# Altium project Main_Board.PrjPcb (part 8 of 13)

## Sheet Power_48_20V@3A.SchDoc
size A3
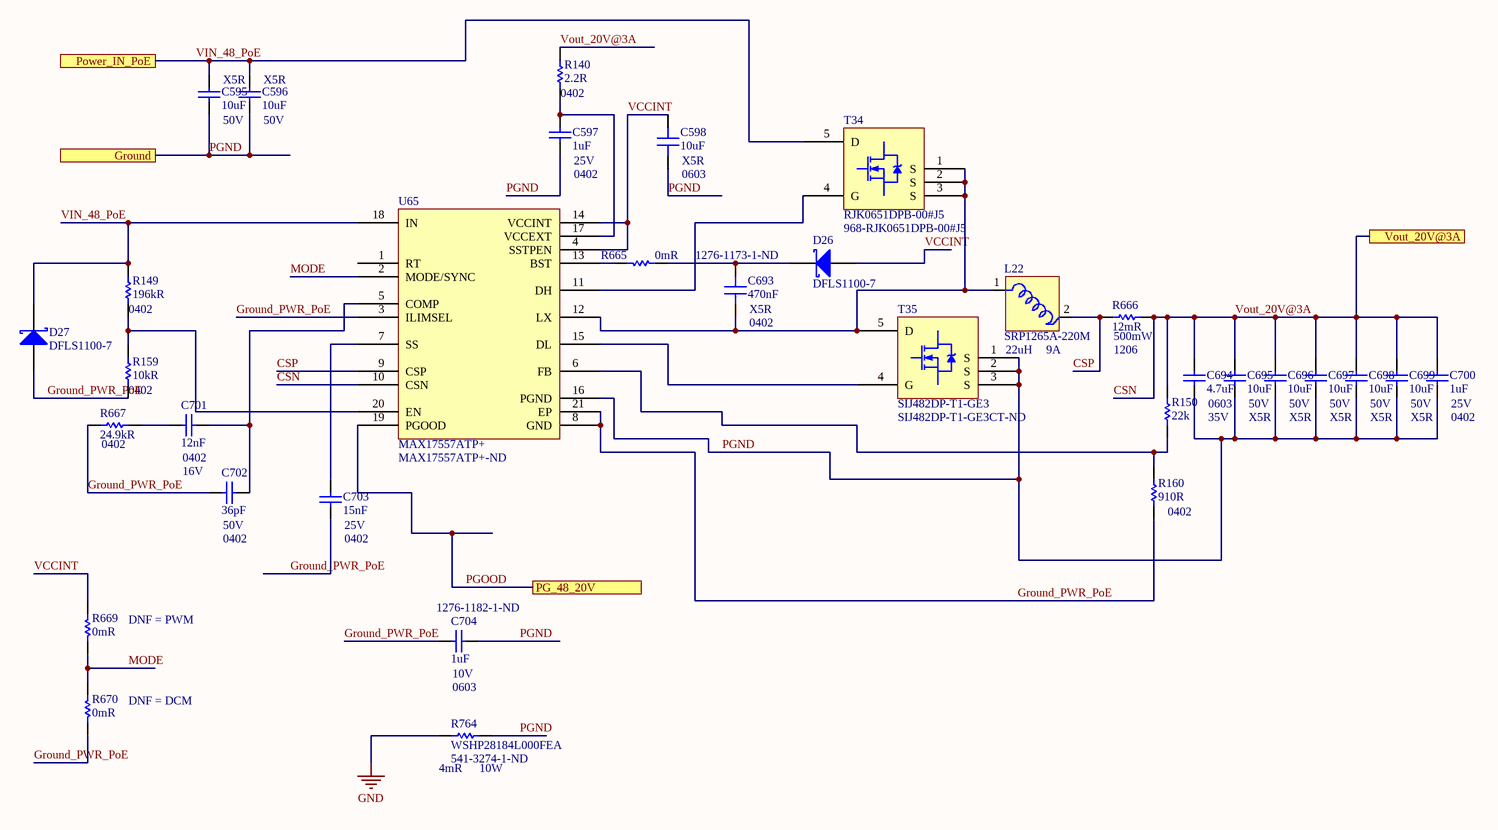
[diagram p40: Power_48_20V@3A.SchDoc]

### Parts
C595  10uF  Voltage Rating (DC): 50V  Dielectric: X5R  [CAP 0805/2012 RF]
C596  10uF  Voltage Rating (DC): 50V  Dielectric: X5R  [CAP 0805/2012 RF]
C597  1uF  Case/Package: 0402  Voltage Rating: 25V  [CAP 0402/1005 KK]
C598  10uF  Case/Package: 0603  Dielectric: X5R  [CAP 0603/1608 RF]
C693  470nF  Supplier Part Number 1: 1276-1173-1-ND  Case/Package: 0402  Dielectric: X5R  [CAP 0402/1005 KK]
C694  4.7uF  Case/Package: 0603  Voltage Rating: 35V  [CAP 0603/1608 RF]
C695  10uF  Voltage Rating (DC): 50V  Dielectric: X5R  [CAP 0805/2012 RF]
C696  10uF  Voltage Rating (DC): 50V  Dielectric: X5R  [CAP 0805/2012 RF]
C697  10uF  Voltage Rating (DC): 50V  Dielectric: X5R  [CAP 0805/2012 RF]
C698  10uF  Voltage Rating (DC): 50V  Dielectric: X5R  [CAP 0805/2012 RF]
C699  10uF  Voltage Rating (DC): 50V  Dielectric: X5R  [CAP 0805/2012 RF]
C700  1uF  Case/Package: 0402  Voltage Rating: 25V  [CAP 0402/1005 KK]
C701  12nF  Case/Package: 0402  Voltage Rating: 16V  [CAP 0402/1005 KK]
C702  36pF  Case Code (Imperial): 0402  Voltage Rating (DC): 50V  [CAP 0402/1005 KK]
C703  15nF  Case/Package: 0402  Voltage Rating: 25V  [CAP 0402/1005 KK]
C704  1uF  Supplier Part Number 1: 1276-1182-1-ND  Case/Package: 0603  Voltage Rating: 10V  [CAP 0603/1608 RF]
D26  DFLS1100-7  [DFLS1100]
D27  DFLS1100-7  [DFLS1100]
L22  SRP1265A-220M  Max DC Current: 9A  Inductance: 22uH  [SRP1265A-220M]
R140  2.2R  Case Code (Imperial): 0402  [RES 0402/1005 RF KK]
R149  196kR  Case/Package: 0402  [RES 0402/1005 RF KK]
R150  22k  [RES 0402/1005 RF KK]
R159  10kR  Case Code (Imperial): 0402  [RES 0402/1005 RF KK]
R160  910R  Case/Package: 0402  [RES 0402/1005 RF KK]
R665  0mR  [RES 0402/1005 RF KK]
R666  12mR  Case/Package: 1206  Max Power Dissipation: 500mW  [RES 1206/3216]
R667  24.9kR  Case/Package: 0402  [RES 0402/1005 RF KK]
R669  0mR  [RES 0402/1005 RF KK]
R670  0mR  [RES 0402/1005 RF KK]
R764  WSHP28184L000FEA  Resistance: 4mR  Max Power Dissipation: 10W  Supplier Part Number 1: 541-3274-1-ND  [WSHP2818]
T34  RJK0651DPB-00#J5  Supplier Part Number 1: 968-RJK0651DPB-00#J5  [RJK0651DPB]
T35  SIJ482DP-T1-GE3  Supplier Part Number 1: SIJ482DP-T1-GE3CT-ND  [SiJ482DP]
U65  MAX17557ATP+  Supplier Part Number 1: MAX17557ATP+-ND  [MAX17557]

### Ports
Ground, PG_48_20V, Power_IN_PoE, Vout_20V@3A

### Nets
GND: R764.1  [project net B503_Ground]
CSN: C694.2 C695.2 C696.2 C697.2 C698.2 C699.2 C700.2 R140.2 R150.2 R666.2 U65.10(CSN) ; port Vout_20V@3A  [also labelled Vout_20V@3A]
CSP: L22.2 R666.1 U65.9(CSP)
Ground_PWR_PoE: C702.1 C703.1 C704.1 D27.2(A) R159.1 R160.1 R667.1 R670.2 U65.3(ILIMSEL) U65.8(GND) U65.21(EP)
MODE: R669.2 R670.1 U65.2(MODE/SYNC)
PGND: C595.1 C596.1 C597.1 C598.1 C694.1 C695.1 C696.1 C697.1 C698.1 C699.1 C700.1 C704.2 R764.2 T35.1(S) T35.2(S) T35.3(S) U65.16(PGND) ; port Ground
PGOOD: U65.19(PGOOD) ; port PG_48_20V  [project net PG_48_20V]
VCCINT: C598.2 D26.2(A) R669.1 U65.4(SSTPEN) U65.14(VCCINT)
VIN_48_PoE: C595.2 C596.2 D27.1(K) R149.2 T34.5(D) U65.18(IN) ; port Power_IN_PoE  [project net V_PoE+]
NetC597_2: C597.2 R140.1 U65.17(VCCEXT)
NetC693_1: C693.1 L22.1 T34.1(S) T34.2(S) T34.3(S) T35.5(D) U65.12(LX)
NetC693_2: C693.2 D26.1(K) R665.1
NetC701_1: C701.1 R667.2
NetC701_2: C701.2 C702.2 U65.5(COMP)
NetC703_2: C703.2 U65.7(SS)
NetR149_1: R149.1 R159.2 U65.20(EN)
NetR150_1: R150.1 R160.2 U65.6(FB)
NetR665_2: R665.2 U65.13(BST)
NetT34_4: T34.4(G) U65.11(DH)
NetT35_4: T35.4(G) U65.15(DL)

Not connected (* = marked no-connect by the designer): U65 1(RT)

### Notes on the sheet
- (near R669) DNF = PWM
- (near R670) DNF = DCM

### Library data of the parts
C595 C596 C695-C699 = Capacitor: Manufacturer: Murata; Manufacturer Part Number: GRM21BR61H106KE43L; Tolerance: 10%
C597 C700 = Capacitor: MURATA - GRT155R61E105KE01D - SMD Multilayer Ceramic Capacitor, 1 µF, 25 V, 0402 [1005 Metric], ± 10%, X5R, GRT Series - SMD Multilayer Ceramic Capacitor, 1 µF, 25 V, 0402 [1005 Metric], ± 10%, X5R, GRT Series
C598 = Capacitor: Manufacturer: Murata; Manufacturer Part Number: GRM188R61A106KE69D; Tolerance: 10%; Voltage Rating: 10V
C693 = Capacitor: Manufacturer: Samsung; Manufacturer Part Number: CL05A474KP5NNNC; Tolerance: 10%; Voltage Rating: 10V
C694 = Capacitor: 0603 4.7 uF 35 V ±10% Tolerance X5R Multilayer Ceramic Chip Capacitor; Manufacturer: Murata; Manufacturer Part Number: GRM188R6YA475KE15D
C701 = Capacitor: CAP, MLCC, X7R, 0.012UF, 16V, 0402; Product Range:C Series; Capacitance:0.012 F; Capacitance Tolerance: 10%; Dielectric Characteristic:X7R; Voltage Rating:16V; Ceramic Capacitor Case:0402 [1005 Metric]; Operating Temperature ;RoHS Compliant: Yes; Manufacturer: KEMET; Manufacturer Part Number: C0402C123K4RACTU; Dissipation Factor: 3.5%
C702 = Capacitor: Ceramic Capacitor 36PF 50V, C0G, 5%, 0402, Full Reel; Manufacturer: Kyocera AVX; Manufacturer Part Number: 04025A360JAT2A
C703 = Capacitor: Cap Ceramic 0.015uF 25V X7R 10% SMD 0402 125C Paper T/R; Manufacturer: Yageo; Manufacturer Part Number: CC0402KRX7R8BB153
C704 = Capacitor: Cap Ceramic 1uF 10V X5R 10% SMD 0603 85C Paper T/R; Manufacturer: Samsung; Manufacturer Part Number: CL10A105KP8NNNC
D26 D27 = DFLS1100-7: DIODE SCHOTTKY 100V POWERDI123; Manufacturer: Diodes; Forward Voltage: 770mV; Forward Current: 1A; Peak Reverse Current: 1uA; Peak Non-Repetitive Surge Current: 50A; Max Forward Surge Current (Ifsm): 40A; Element Configuration: Single; Polarity: Standard; Capacitance: 36pF
L22 = SRP1265A-220M: Inductor Power Shielded Wirewound 22uH 20% 100KHz 20Q-Factor Carbonyl Powder 9A 37mOhm DCR Automotive T/R; Manufacturer: Bourns; Saturation Current: 12A; DC Resistance (DCR): 37mR; Self Resonant Frequency: 6MHz
R140 = Resistor: RES SMD 2.2 OHM 5% 1/16W 0402; Manufacturer: Yageo; Manufacturer Part Number: RC0402JR-072R2L; Power Rating: 62.5mW; Voltage Rating: 50V; Temperature Coefficient: 200ppm/°C; Max Power Dissipation: 63mW
R149 = Resistor: Thick Film Resistors - SMD 196K OHM 1%; Manufacturer: Yageo; Manufacturer Part Number: RC0402FR-07196KL; Power Rating: 62.5mW; Voltage Rating: 50V; Temperature Coefficient: 100ppm/°C; Max Power Dissipation: 63mW
R150 = Resistor: TE CONNECTIVITY - CRGCQ0402F22K - RES, 22K, 1%, 0402, THICK FILM
R159 = Resistor: Surface Mount Thick Film Resistor, Rc Series, 10 Kohm, 62.5 Mw, - 1%, 50 V, 0402 [1005 Metric]; Manufacturer: Yageo; Manufacturer Part Number: RC0402FR-0710KL; Voltage Rating: 50V; Power Rating: 62.5mW; Temperature Coefficient: 100ppm/°C
R160 = Resistor: RES SMD 910 OHM 5% 1/10W 0402; Manufacturer: Panasonic; Manufacturer Part Number: ERJ2GEJ911X; Power Rating: 100mW; Voltage Rating: 50V; Temperature Coefficient: 200ppm/°C
R665 R669 R670 = Resistor: Manufacturer 1: Yageo; Manufacturer Part Number 1: RC0402JR-070RL; Power Rating: 62.5mW; Tolerance: 5%; Voltage Rating: 50V; Max Power Dissipation: 63mW; Temperature Coefficient: 200ppm/°C
R666 = Resistor: RES 0.012 OHM 1% 1/2W 1206; Manufacturer: Stackpole Electronics; Manufacturer Part Number: CSR1206FK12L0; Temperature Coefficient: 100ppm/°C
R667 = Resistor: RES SMD 24.9KOHM 0.1% 1/16W 0402; Manufacturer: Panasonic; Manufacturer Part Number: ERA-2AEB2492X; Power Rating: 63mW; Voltage Rating: 25V; Temperature Coefficient: 25ppm/°C; Voltage Rating (DC): 50V
R764 = WSHP28184L000FEA: RES 0.004 OHM 1% 10W 2818; Manufacturer: Vishay; Temperature Coefficient: 200ppm/°C
T34 = RJK0651DPB-00#J5: MOSFET N-CH 60V 25A LFPAK; Manufacturer: Renesas; Rise Time: 4.4ns; Turn-On Delay Time: 8.4ns; Turn-Off Delay Time: 42ns; Fall Time: 6.8ns; Gate to Source Voltage (Vgs): 20V; Rds On Max: 14mR; Input Capacitance: 2.03nF; Max Power Dissipation: 45W; Number of Elements: 1
T35 = SIJ482DP-T1-GE3: MOSFET 80V 6.2mOhm@10V 60A N-Ch MV T-FET; Manufacturer: Vishay; Rds On Max: 6.2mR; Input Capacitance: 2.425nF; Gate to Source Voltage (Vgs): 20V; Power Dissipation: 69.4W; Turn-Off Delay Time: 72ns; Number of Elements: 1; Element Configuration: Single; On-State Resistance: 9.5MR; Turn-On Delay Time: 28ns; Threshold Voltage: 1.5V
U65 = MAX17557ATP+: IC REG CTRLR BUCK 20-TQFN; Manufacturer: Maxim

## Sheet UM78M_12_8V.SchDoc
size A4
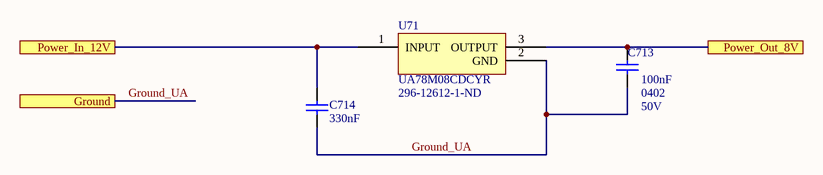
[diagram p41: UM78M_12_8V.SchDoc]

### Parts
C713  100nF  Case Code (Imperial): 0402  Voltage: 50V  [CAP 0402/1005 KK]
C714  330nF  [CAP 0603/1608 RF]
U71  UA78M08CDCYR  Supplier Part Number 1: 296-12612-1-ND  [UA78M]

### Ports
Ground, Power_In_12V, Power_Out_8V

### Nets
12V_LT3042: C714.2 U71.1(INPUT) ; port Power_In_12V
Ground_UA: C713.1 C714.1 U71.2(GND) ; port Ground  [project net AGND]
NetC713_2: C713.2 U71.3(OUTPUT) ; port Power_Out_8V

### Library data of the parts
C713 = Capacitor: CAP CER 0.1UF 50V X5R 0402; Manufacturer: Murata; Manufacturer Part Number: GRM155R61H104KE14D; Dielectric Material: Ceramic; Dissipation Factor: 0.025%; Tolerance: 10%
C714 = Capacitor: CAP CER 0.33UF 25V Y5V 0603; Manufacturer: KEMET; Manufacturer Part Number: C0603C334Z3VACTU; Dielectric Material: Ceramic; Tolerance: 80%; Dissipation Factor: 7%
U71 = UA78M08CDCYR: IC REG LINEAR 8V 500MA SOT223-4; Manufacturer: Texas Instruments; Dropout Voltage: 2V; Number of Outputs: 1; Max Input Voltage: 25V; Min Input Voltage: 10.5V; Polarity: Positive; Power Supply Rejection Ratio (PSRR): 80dB; Quiescent Current: 4.6mA; Output Type: Fixed

## Sheet TPS7A88_3V3_1V8_0V9V@2x1A.SchDoc
size A4
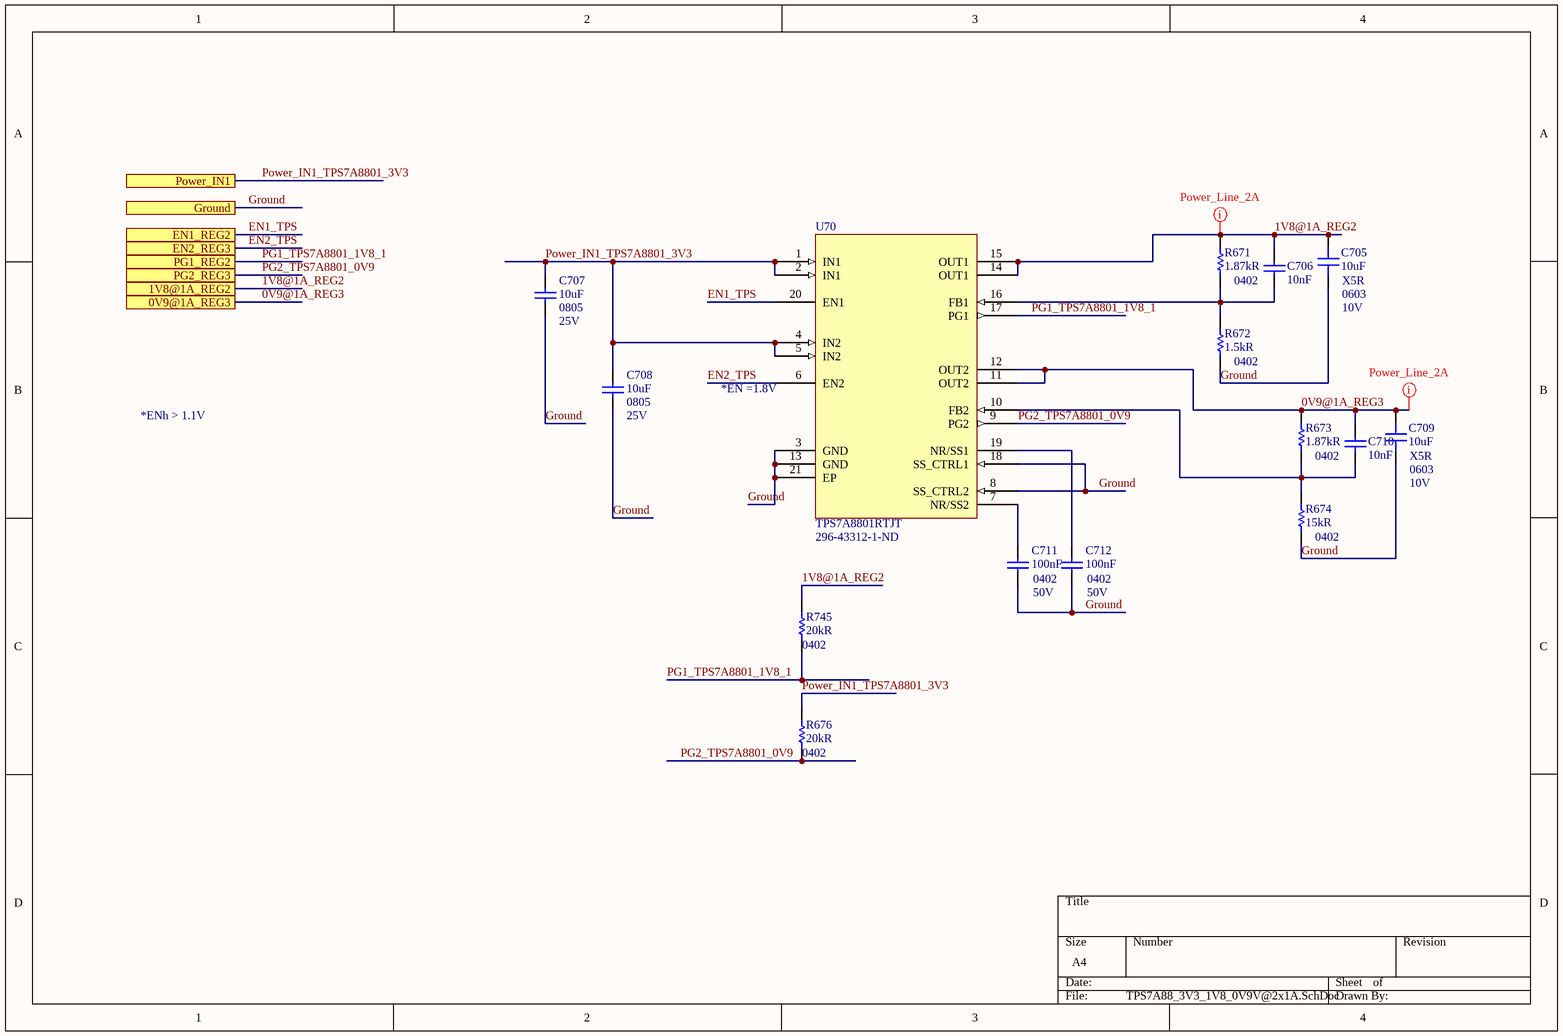
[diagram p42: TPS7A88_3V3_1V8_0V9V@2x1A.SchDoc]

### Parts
C705  10uF  Case/Package: 0603  Dielectric: X5R  Voltage Rating: 10V  [CAP 0603/1608 RF]
C706  10nF  [CAP 0201/0603 KK]
C707  10uF  Case/Package: 0805  Voltage Rating: 25V  [CAP 0805/2012 RF]
C708  10uF  Case/Package: 0805  Voltage Rating: 25V  [CAP 0805/2012 RF]
C709  10uF  Case/Package: 0603  Dielectric: X5R  Voltage: 10V  [CAP 0603/1608 RF]
C710  10nF  [CAP 0201/0603 KK]
C711  100nF  Case Code (Imperial): 0402  Voltage: 50V  [CAP 0402/1005 KK]
C712  100nF  Case Code (Imperial): 0402  Voltage: 50V  [CAP 0402/1005 KK]
R671  1.87kR  Case/Package: 0402  [RES 0402/1005 RF KK]
R672  1.5kR  Case/Package: 0402  [RES 0402/1005 RF KK]
R673  1.87kR  Case/Package: 0402  [RES 0402/1005 RF KK]
R674  15kR  Case Code (Imperial): 0402  [RES 0402/1005 RF KK]
R676  20kR  Case/Package: 0402  [RES 0402/1005 RF KK]
R745  20kR  Case/Package: 0402  [RES 0402/1005 RF KK]
U70  TPS7A8801RTJT  Supplier Part Number 1: 296-43312-1-ND  [TPS7A88]

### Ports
0V9@1A_REG3, 1V8@1A_REG2, EN1_REG2, EN2_REG3, Ground, PG1_REG2, PG2_REG3, Power_IN1

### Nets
Ground: C705.1 C707.1 C708.1 C709.1 C711.1 C712.1 R672.1 R674.1 U70.3(GND) U70.8(SS_CTRL2) U70.13(GND) U70.18(SS_CTRL1) U70.21(EP) ; port Ground  [project net B503_Ground]
0V9@1A_REG3: C709.2 C710.2 R673.2 U70.11(OUT2) U70.12(OUT2) ; port 0V9@1A_REG3
1V8@1A_REG2: C705.2 C706.2 R671.2 R745.1 U70.14(OUT1) U70.15(OUT1) ; port 1V8@1A_REG2  [project net 1V8@0.5A_ADC_filtered]
EN1_TPS: U70.20(EN1) ; port EN1_REG2
EN2_TPS: R745.2 U70.6(EN2) U70.17(PG1) ; port EN2_REG3, port PG1_REG2  [also labelled PG1_TPS7A8801_1V8_1]
PG2_TPS7A8801_0V9: R676.2 U70.9(PG2) ; port PG2_REG3
Power_IN1_TPS7A8801_3V3: C707.2 C708.2 R676.1 U70.1(IN1) U70.2(IN1) U70.4(IN2) U70.5(IN2) ; port Power_IN1  [project net 3V3_RAIL]
NetC706_1: C706.1 R671.1 R672.2 U70.16(FB1)
NetC710_1: C710.1 R673.1 R674.2 U70.10(FB2)
NetC711_2: C711.2 U70.7(NR/SS2)
NetC712_2: C712.2 U70.19(NR/SS1)

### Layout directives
net class Power_Line_2A: 0V9@1A_REG3, 1V8@0.5A_ADC_filtered

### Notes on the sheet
- *ENh > 1.1V
- (near U70) *EN =1.8V

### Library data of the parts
C705 C709 = Capacitor: Manufacturer: Murata; Manufacturer Part Number: GRM188R61A106KE69D; Tolerance: 10%
C706 C710 = Capacitor: CAP CER 10000PF 16V X7R 0201; Manufacturer: Murata; Manufacturer Part Number: GRM033R71C103KE14D; Tolerance: 10%
C707 C708 = Capacitor: CAP CER 10UF 25V X5R 0805; Manufacturer: KEMET; Manufacturer Part Number: C0805C106K3PACTU; Dielectric Material: Ceramic; Dissipation Factor: 10%
C711 C712 = Capacitor: as C713 on sheet UM78M_12_8V
R671 R673 = Resistor: Manufacturer: Panasonic; Manufacturer Part Number: ERA-2AEB1871X; Power Rating: 62.5mW; Tolerance: 0.1%; Temperature Coefficient: 25ppm/°C; Max Power Dissipation: 63mW
R672 = Resistor: Manufacturer: Panasonic; Manufacturer Part Number: ERA-2AEB152X; Power Rating: 63mW; Tolerance: 0.1%; Voltage Rating: 25V; Temperature Coefficient: 25ppm/°C
R674 = Resistor: Manufacturer: Panasonic; Manufacturer Part Number: ERJ-2RKF1502X; Tolerance: 1%; Voltage Rating: 50V; Power Rating: 100mW; Temperature Coefficient: 100ppm/°C
R676 R745 = Resistor: Manufacturer: Panasonic; Manufacturer Part Number: ERJ-2RKF2002X; Power Rating: 100mW; Tolerance: 1%; Voltage Rating: 50V; Temperature Coefficient: 100ppm/°C
U70 = TPS7A8801RTJT: IC REG LINEAR POS ADJ 1A 20QFN; Manufacturer: Texas Instruments; Output Voltage: 5V; Number of Regulators: 2; Min Current Limit: 1.5A; Quiescent Current: 2mA; Dropout Voltage: 130mV

## Sheet ADP1741_3V3_0V85.SchDoc
size A4
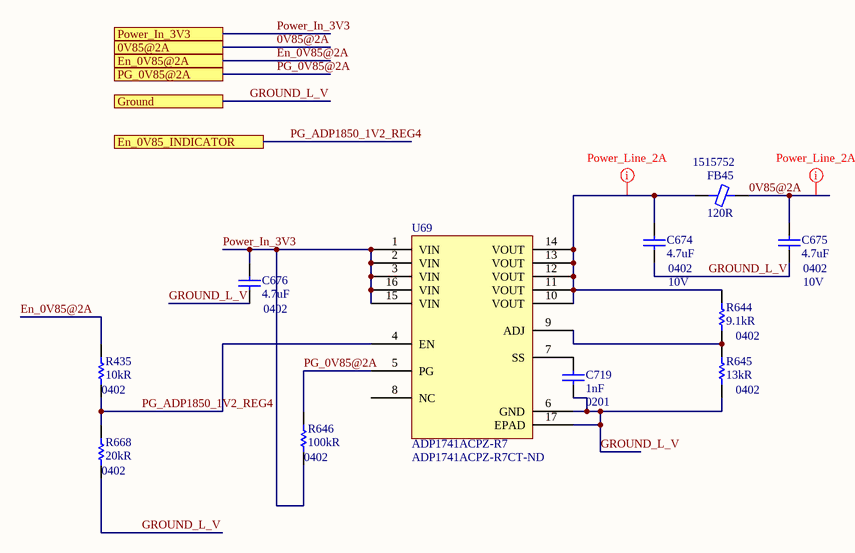
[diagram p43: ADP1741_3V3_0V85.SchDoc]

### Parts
C674  4.7uF  Case/Package: 0402  Voltage Rating: 10V  [CAP 0402/1005 KK]
C675  4.7uF  Case/Package: 0402  Voltage Rating: 10V  [CAP 0402/1005 KK]
C676  4.7uF  Case/Package: 0402  [CAP 0402/1005 KK]
C719  1nF  Case/Package: 0201  [CAP 0201/0603 KK]
FB45  120R  Supplier Part Number 1: 1515752  [FER 0603/1608]
R435  10kR  Case Code (Imperial): 0402  [RES 0402/1005 RF KK]
R644  9.1kR  Case/Package: 0402  [RES 0402/1005 RF KK]
R645  13kR  Case Code (Imperial): 0402  [RES 0402/1005 RF KK]
R646  100kR  Case/Package: 0402  [RES 0402/1005 RF KK]
R668  20kR  Case/Package: 0402  [RES 0402/1005 RF KK]
U69  ADP1741ACPZ-R7  Supplier Part Number 1: ADP1741ACPZ-R7CT-ND  [ADP1752_1753/ADP1740_1741]

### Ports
0V85@2A, En_0V85@2A, En_0V85_INDICATOR, Ground, PG_0V85@2A, Power_In_3V3

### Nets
GROUND_L_V: C674.1 C675.1 C676.1 C719.1 R645.1 R668.2 U69.6(GND) U69.17(EPAD) ; port Ground  [project net B503_Ground]
0V85@2A: C675.2 FB45.2 ; port 0V85@2A
En_0V85@2A: R435.2 ; port En_0V85@2A
PG_0V85@2A: R646.2 U69.5(PG) ; port PG_0V85@2A  [project net EN_SEQ_LT3504]
PG_ADP1850_1V2_REG4: R435.1 R668.1 U69.4(EN) ; port En_0V85_INDICATOR
Power_In_3V3: C676.2 R646.1 U69.1(VIN) U69.2(VIN) U69.3(VIN) U69.15(VIN) U69.16(VIN) ; port Power_In_3V3  [project net 3V3_RAIL]
NetC674_2: C674.2 FB45.1 R644.2 U69.10(VOUT) U69.11(VOUT) U69.12(VOUT) U69.13(VOUT) U69.14(VOUT)
NetC719_2: C719.2 U69.7(SS)
NetR644_1: R644.1 R645.2 U69.9(ADJ)

Not connected (* = marked no-connect by the designer): U69 8(NC)

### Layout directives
net class Power_Line_2A: 0V85@2A, NetC674_2

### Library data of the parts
C674 C675 = Capacitor: 0402 10 V 4.7 uF ±20% Tolerance X5R Multilayer Ceramic Chip Capacitor; Manufacturer: Murata; Manufacturer Part Number: GRM155R61A475MEAAD
C676 = Capacitor: 0402 10 V 4.7 uF ±20% Tolerance X5R Multilayer Ceramic Chip Capacitor; Manufacturer: Murata; Manufacturer Part Number: GRM155R61A475MEAAD; Voltage Rating: 10V
C719 = Capacitor: CAP CER 1000PF 25V X5R 0201; Manufacturer: Murata; Manufacturer Part Number: GRM033R61E102KA01D; Tolerance: 10%
FB45 = Ferrite: Ind Chip Bead 120Ohm 25% 100MHz Ferrite 3A 0603 Paper T/R; Manufacturer: Murata; Manufacturer Part Number: BLM18SG121TN1D; Material: Steel,Ferrite; DC Resistance (DCR): 25mR; Number of Circuits: 1; Shielding: Unshielded
R435 = Resistor: Manufacturer: Yageo; Manufacturer Part Number: RC0402FR-0710KL; Voltage Rating: 50V; Power Rating: 62.5mW; Tolerance: 1%; Temperature Coefficient: 100ppm/°C
R644 = Resistor: Manufacturer: Vishay; Manufacturer Part Number: CRCW04029K10FKED; Power Rating: 63mW; Tolerance: 1%; Voltage Rating: 50V; Temperature Coefficient: 100ppm/°C
R645 = Resistor: Manufacturer: Panasonic; Manufacturer Part Number: ERA-2AED133X; Power Rating: 62.5mW; Tolerance: 0.5%; Temperature Coefficient: 25ppm/°C; Max Power Dissipation: 63mW
R646 = Resistor: Manufacturer 1: Panasonic; Manufacturer Part Number 1: ERA-2AED104X; Tolerance: 0.5%; Power Rating: 63mW; Voltage Rating: 25V; Temperature Coefficient: 25ppm/°C
R668 = Resistor: as R676 on sheet TPS7A88_3V3_1V8_0V9V@2x1A
U69 = ADP1741ACPZ-R7: IC REG LIN POS ADJ 2A 16LFCSP; Manufacturer: Analog Devices; Output Voltage: 3V; Max Input Voltage: 3.6V; Min Input Voltage: 1.6V; Min Output Voltage: 750mV; Operating Supply Current: 1.8mA; Power Supply Rejection Ratio (PSRR): 70dB; Dropout Voltage: 160mV; Number of Outputs: 1; Min Current Limit: 2.4A; Polarity: Positive; Accuracy: 1%; Output Type: Adjustable

## Sheet ST1L08_5V_0V6.SchDoc
size A3
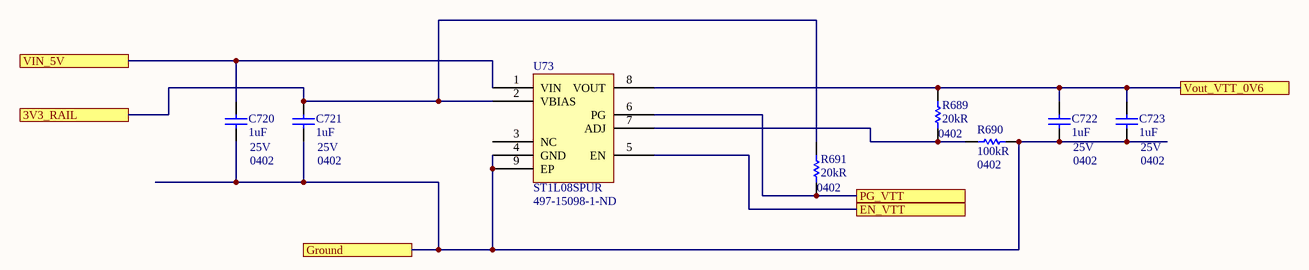
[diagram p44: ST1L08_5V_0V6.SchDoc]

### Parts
C720  1uF  Case/Package: 0402  Voltage Rating: 25V  [CAP 0402/1005 KK]
C721  1uF  Case/Package: 0402  Voltage Rating: 25V  [CAP 0402/1005 KK]
C722  1uF  Case/Package: 0402  Voltage Rating: 25V  [CAP 0402/1005 KK]
C723  1uF  Case/Package: 0402  Voltage Rating: 25V  [CAP 0402/1005 KK]
R689  20kR  Case/Package: 0402  [RES 0402/1005 RF KK]
R690  100kR  Case/Package: 0402  [RES 0402/1005 RF KK]
R691  20kR  Case/Package: 0402  [RES 0402/1005 RF KK]
U73  ST1L08SPUR  Supplier Part Number 1: 497-15098-1-ND  [ST1L08]

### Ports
3V3_RAIL, EN_VTT, Ground, PG_VTT, VIN_5V, Vout_VTT_0V6

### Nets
B503_Ground: C720.1 C721.1 C722.1 C723.1 R690.1 U73.4(GND) U73.9(EP) ; port Ground
3V3_RAIL: C721.2 R691.1 U73.2(VBIAS) ; port 3V3_RAIL
5V_RAIL: C720.2 U73.1(VIN) ; port VIN_5V
GPIOb_02.GPIO4: R691.2 U73.6(PG) ; port PG_VTT
PG2_TPS7A8801_0V9: U73.5(EN) ; port EN_VTT
RAM_DDR4_VTT: C722.2 C723.2 R689.1 U73.8(VOUT) ; port Vout_VTT_0V6
NetR689_2: R689.2 R690.2 U73.7(ADJ)

Not connected (* = marked no-connect by the designer): U73 3(NC)

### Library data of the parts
C720-C723 = Capacitor: as C597 on sheet Power_48_20V@3A
R689 R691 = Resistor: as R676 on sheet TPS7A88_3V3_1V8_0V9V@2x1A
R690 = Resistor: as R646 on sheet ADP1741_3V3_0V85
U73 = ST1L08SPUR: IC REG LINEAR POS ADJ 800MA 8DFN; Manufacturer: STMicroelectronics; Number of Outputs: 1; Min Input Voltage: 1V; Max Input Voltage: 5.5V; Output Voltage: 4V; Dropout Voltage: 700mV; Polarity: Positive; Accuracy: 2%; Quiescent Current: 150uA; Operating Supply Current: 200nA; Power Supply Rejection Ratio (PSRR): 80dB; Output Type: Adjustable

## Sheet Power_LED.SchDoc: Power_Led
size A3
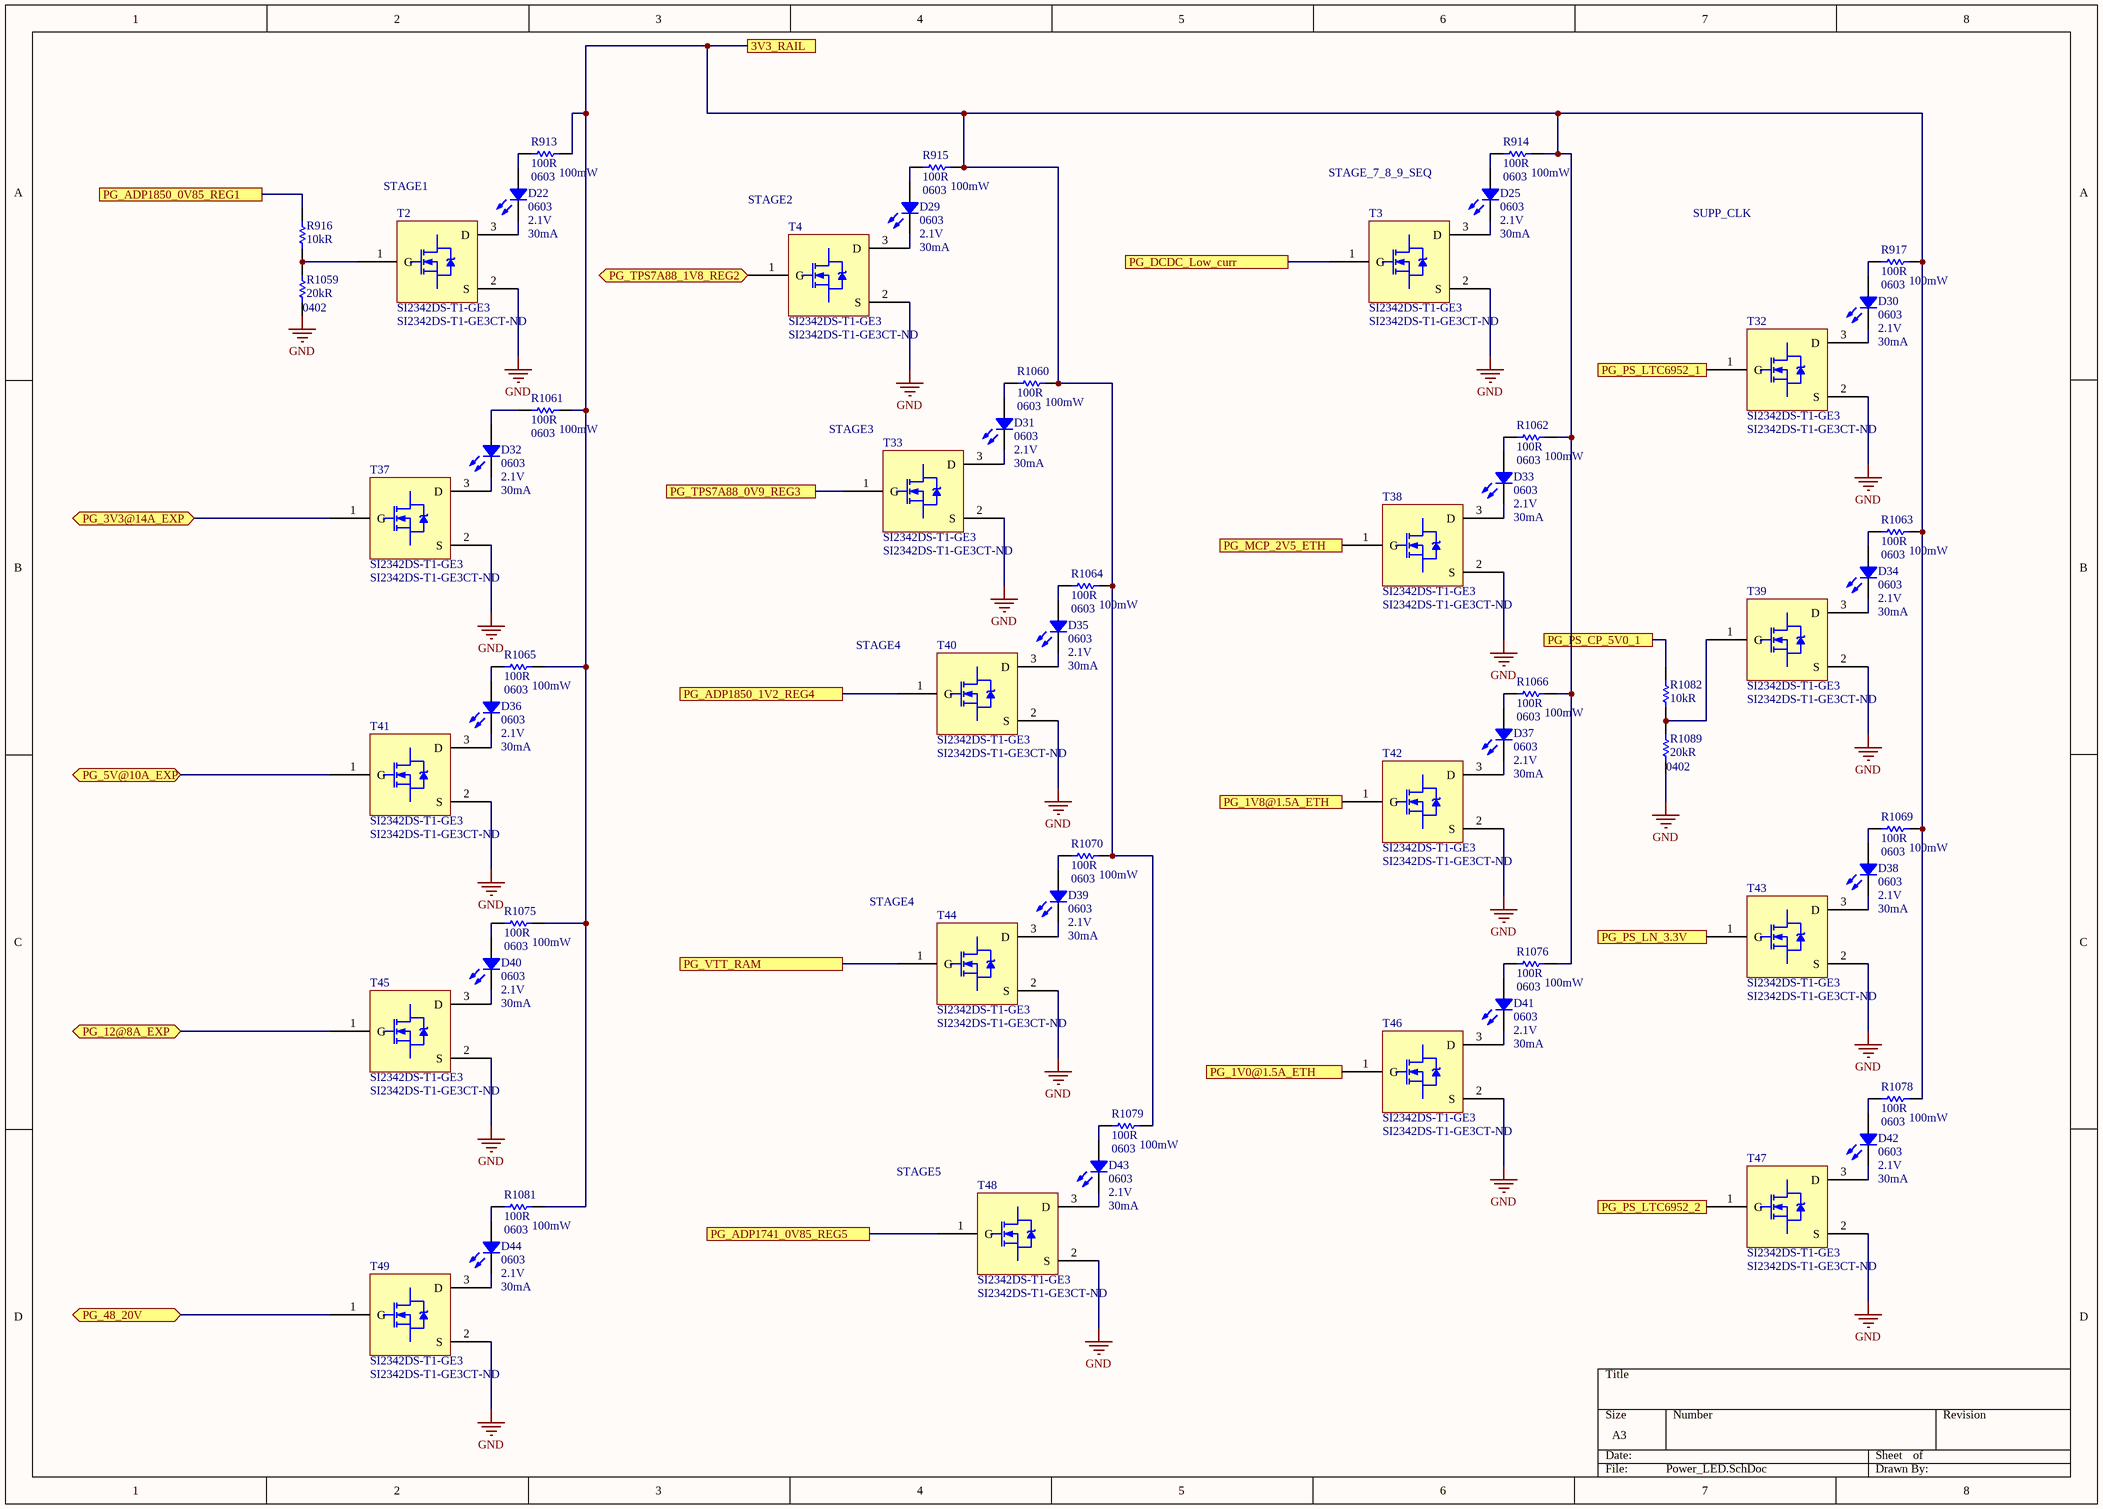
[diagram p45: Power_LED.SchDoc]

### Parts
D22  Case Code (Imperial): 0603  Forward Voltage: 2.1V  Forward Current: 30mA  [LED 0603/1608 GREEN]  (hidden comment: LTST-C190GKT)
D25  Case Code (Imperial): 0603  Forward Voltage: 2.1V  Forward Current: 30mA  [LED 0603/1608 GREEN]  (hidden comment: LTST-C190GKT)
D29  Case Code (Imperial): 0603  Forward Voltage: 2.1V  Forward Current: 30mA  [LED 0603/1608 GREEN]  (hidden comment: LTST-C190GKT)
D30  Case Code (Imperial): 0603  Forward Voltage: 2.1V  Forward Current: 30mA  [LED 0603/1608 GREEN]  (hidden comment: LTST-C190GKT)
D31  Case Code (Imperial): 0603  Forward Voltage: 2.1V  Forward Current: 30mA  [LED 0603/1608 GREEN]  (hidden comment: LTST-C190GKT)
D32  Case Code (Imperial): 0603  Forward Voltage: 2.1V  Forward Current: 30mA  [LED 0603/1608 GREEN]  (hidden comment: LTST-C190GKT)
D33  Case Code (Imperial): 0603  Forward Voltage: 2.1V  Forward Current: 30mA  [LED 0603/1608 GREEN]  (hidden comment: LTST-C190GKT)
D34  Case Code (Imperial): 0603  Forward Voltage: 2.1V  Forward Current: 30mA  [LED 0603/1608 GREEN]  (hidden comment: LTST-C190GKT)
D35  Case Code (Imperial): 0603  Forward Voltage: 2.1V  Forward Current: 30mA  [LED 0603/1608 GREEN]  (hidden comment: LTST-C190GKT)
D36  Case Code (Imperial): 0603  Forward Voltage: 2.1V  Forward Current: 30mA  [LED 0603/1608 GREEN]  (hidden comment: LTST-C190GKT)
D37  Case Code (Imperial): 0603  Forward Voltage: 2.1V  Forward Current: 30mA  [LED 0603/1608 GREEN]  (hidden comment: LTST-C190GKT)
D38  Case Code (Imperial): 0603  Forward Voltage: 2.1V  Forward Current: 30mA  [LED 0603/1608 GREEN]  (hidden comment: LTST-C190GKT)
D39  Case Code (Imperial): 0603  Forward Voltage: 2.1V  Forward Current: 30mA  [LED 0603/1608 GREEN]  (hidden comment: LTST-C190GKT)
D40  Case Code (Imperial): 0603  Forward Voltage: 2.1V  Forward Current: 30mA  [LED 0603/1608 GREEN]  (hidden comment: LTST-C190GKT)
D41  Case Code (Imperial): 0603  Forward Voltage: 2.1V  Forward Current: 30mA  [LED 0603/1608 GREEN]  (hidden comment: LTST-C190GKT)
D42  Case Code (Imperial): 0603  Forward Voltage: 2.1V  Forward Current: 30mA  [LED 0603/1608 GREEN]  (hidden comment: LTST-C190GKT)
D43  Case Code (Imperial): 0603  Forward Voltage: 2.1V  Forward Current: 30mA  [LED 0603/1608 GREEN]  (hidden comment: LTST-C190GKT)
D44  Case Code (Imperial): 0603  Forward Voltage: 2.1V  Forward Current: 30mA  [LED 0603/1608 GREEN]  (hidden comment: LTST-C190GKT)
R913  100R  Case/Package: 0603  Power Rating: 100mW  [RES 0603/1608 RF]
R914  100R  Case/Package: 0603  Power Rating: 100mW  [RES 0603/1608 RF]
R915  100R  Case/Package: 0603  Power Rating: 100mW  [RES 0603/1608 RF]
R916  10kR  [RES 0402/1005 RF KK]
R917  100R  Case/Package: 0603  Power Rating: 100mW  [RES 0603/1608 RF]
R1059  20kR  Case/Package: 0402  [RES 0402/1005 RF KK]
R1060  100R  Case/Package: 0603  Power Rating: 100mW  [RES 0603/1608 RF]
R1061  100R  Case/Package: 0603  Power Rating: 100mW  [RES 0603/1608 RF]
R1062  100R  Case/Package: 0603  Power Rating: 100mW  [RES 0603/1608 RF]
R1063  100R  Case/Package: 0603  Power Rating: 100mW  [RES 0603/1608 RF]
R1064  100R  Case/Package: 0603  Power Rating: 100mW  [RES 0603/1608 RF]
R1065  100R  Case/Package: 0603  Power Rating: 100mW  [RES 0603/1608 RF]
R1066  100R  Case/Package: 0603  Power Rating: 100mW  [RES 0603/1608 RF]
R1069  100R  Case/Package: 0603  Power Rating: 100mW  [RES 0603/1608 RF]
R1070  100R  Case/Package: 0603  Power Rating: 100mW  [RES 0603/1608 RF]
R1075  100R  Case/Package: 0603  Power Rating: 100mW  [RES 0603/1608 RF]
R1076  100R  Case/Package: 0603  Power Rating: 100mW  [RES 0603/1608 RF]
R1078  100R  Case/Package: 0603  Power Rating: 100mW  [RES 0603/1608 RF]
R1079  100R  Case/Package: 0603  Power Rating: 100mW  [RES 0603/1608 RF]
R1081  100R  Case/Package: 0603  Power Rating: 100mW  [RES 0603/1608 RF]
R1082  10kR  [RES 0402/1005 RF KK]
R1089  20kR  Case/Package: 0402  [RES 0402/1005 RF KK]
T2  SI2342DS-T1-GE3  Supplier Part Number 1: SI2342DS-T1-GE3CT-ND  [SI2342DS-T1-GE3]
T3  SI2342DS-T1-GE3  Supplier Part Number 1: SI2342DS-T1-GE3CT-ND  [SI2342DS-T1-GE3]
T4  SI2342DS-T1-GE3  Supplier Part Number 1: SI2342DS-T1-GE3CT-ND  [SI2342DS-T1-GE3]
T32  SI2342DS-T1-GE3  Supplier Part Number 1: SI2342DS-T1-GE3CT-ND  [SI2342DS-T1-GE3]
T33  SI2342DS-T1-GE3  Supplier Part Number 1: SI2342DS-T1-GE3CT-ND  [SI2342DS-T1-GE3]
T37  SI2342DS-T1-GE3  Supplier Part Number 1: SI2342DS-T1-GE3CT-ND  [SI2342DS-T1-GE3]
T38  SI2342DS-T1-GE3  Supplier Part Number 1: SI2342DS-T1-GE3CT-ND  [SI2342DS-T1-GE3]
T39  SI2342DS-T1-GE3  Supplier Part Number 1: SI2342DS-T1-GE3CT-ND  [SI2342DS-T1-GE3]
T40  SI2342DS-T1-GE3  Supplier Part Number 1: SI2342DS-T1-GE3CT-ND  [SI2342DS-T1-GE3]
T41  SI2342DS-T1-GE3  Supplier Part Number 1: SI2342DS-T1-GE3CT-ND  [SI2342DS-T1-GE3]
T42  SI2342DS-T1-GE3  Supplier Part Number 1: SI2342DS-T1-GE3CT-ND  [SI2342DS-T1-GE3]
T43  SI2342DS-T1-GE3  Supplier Part Number 1: SI2342DS-T1-GE3CT-ND  [SI2342DS-T1-GE3]
T44  SI2342DS-T1-GE3  Supplier Part Number 1: SI2342DS-T1-GE3CT-ND  [SI2342DS-T1-GE3]
T45  SI2342DS-T1-GE3  Supplier Part Number 1: SI2342DS-T1-GE3CT-ND  [SI2342DS-T1-GE3]
T46  SI2342DS-T1-GE3  Supplier Part Number 1: SI2342DS-T1-GE3CT-ND  [SI2342DS-T1-GE3]
T47  SI2342DS-T1-GE3  Supplier Part Number 1: SI2342DS-T1-GE3CT-ND  [SI2342DS-T1-GE3]
T48  SI2342DS-T1-GE3  Supplier Part Number 1: SI2342DS-T1-GE3CT-ND  [SI2342DS-T1-GE3]
T49  SI2342DS-T1-GE3  Supplier Part Number 1: SI2342DS-T1-GE3CT-ND  [SI2342DS-T1-GE3]

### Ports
3V3_RAIL, PG_1V0@1.5A_ETH, PG_1V8@1.5A_ETH, PG_3V3@14A_EXP (bidir), PG_5V@10A_EXP (bidir), PG_12@8A_EXP (bidir), PG_48_20V (bidir), PG_ADP1741_0V85_REG5, PG_ADP1850_0V85_REG1, PG_ADP1850_1V2_REG4, PG_DCDC_Low_curr, PG_MCP_2V5_ETH, PG_PS_CP_5V0_1, PG_PS_LN_3.3V, PG_PS_LTC6952_1, PG_PS_LTC6952_2, PG_TPS7A88_0V9_REG3, PG_TPS7A88_1V8_REG2 (bidir), PG_VTT_RAM

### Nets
GND: R1059.2 R1089.2 T2.2(S) T3.2(S) T4.2(S) T32.2(S) T33.2(S) T37.2(S) T38.2(S) T39.2(S) T40.2(S) T41.2(S) T42.2(S) T43.2(S) T44.2(S) T45.2(S) T46.2(S) T47.2(S) T48.2(S) T49.2(S)  [project net B503_Ground]
3V3_RAIL: R913.2 R914.2 R915.2 R917.2 R1060.2 R1061.2 R1062.2 R1063.2 R1064.2 R1065.2 R1066.2 R1069.2 R1070.2 R1075.2 R1076.2 R1078.2 R1079.2 R1081.2 ; port 3V3_RAIL
ADP1741_PG: T43.1(G) ; port PG_PS_LN_3.3V
EN1_TPS: R916.1 ; port PG_ADP1850_0V85_REG1
EN2_TPS: T4.1(G) ; port PG_TPS7A88_1V8_REG2
EN_SEQ_LT3504: T48.1(G) ; port PG_ADP1741_0V85_REG5
GPIOa_00.GPIO5: T46.1(G) ; port PG_1V0@1.5A_ETH
GPIOa_00.GPIO6: T42.1(G) ; port PG_1V8@1.5A_ETH
GPIOb_02.GPIO4: T44.1(G) ; port PG_VTT_RAM
GPIOb_12.GPIO7: T3.1(G) ; port PG_DCDC_Low_curr
PG2_TPS7A8801_0V9: T33.1(G) ; port PG_TPS7A88_0V9_REG3
PG_2V5@1.5A: T38.1(G) ; port PG_MCP_2V5_ETH
PG_3V3@14A_EXP: T37.1(G) ; port PG_3V3@14A_EXP
PG_5V@10A_EXP: T41.1(G) ; port PG_5V@10A_EXP
PG_12@8A_EXP: T45.1(G) ; port PG_12@8A_EXP
PG_48_20V: T49.1(G) ; port PG_48_20V
PG_ADP1850_1V2_REG4: T40.1(G) ; port PG_ADP1850_1V2_REG4
PG_LT3042: R1082.1 ; port PG_PS_CP_5V0_1
PG_PS_LTC6952_1: T32.1(G) ; port PG_PS_LTC6952_1
PG_PS_LTC6952_2: T47.1(G) ; port PG_PS_LTC6952_2
NetD22_1: D22.1 R913.1
NetD22_2: D22.2 T2.3(D)
NetD25_1: D25.1 R914.1
NetD25_2: D25.2 T3.3(D)
NetD29_1: D29.1 R915.1
NetD29_2: D29.2 T4.3(D)
NetD30_1: D30.1 R917.1
NetD30_2: D30.2 T32.3(D)
NetD31_1: D31.1 R1060.1
NetD31_2: D31.2 T33.3(D)
NetD32_1: D32.1 R1061.1
NetD32_2: D32.2 T37.3(D)
NetD33_1: D33.1 R1062.1
NetD33_2: D33.2 T38.3(D)
NetD34_1: D34.1 R1063.1
NetD34_2: D34.2 T39.3(D)
NetD35_1: D35.1 R1064.1
NetD35_2: D35.2 T40.3(D)
NetD36_1: D36.1 R1065.1
NetD36_2: D36.2 T41.3(D)
NetD37_1: D37.1 R1066.1
NetD37_2: D37.2 T42.3(D)
NetD38_1: D38.1 R1069.1
NetD38_2: D38.2 T43.3(D)
NetD39_1: D39.1 R1070.1
NetD39_2: D39.2 T44.3(D)
NetD40_1: D40.1 R1075.1
NetD40_2: D40.2 T45.3(D)
NetD41_1: D41.1 R1076.1
NetD41_2: D41.2 T46.3(D)
NetD42_1: D42.1 R1078.1
NetD42_2: D42.2 T47.3(D)
NetD43_1: D43.1 R1079.1
NetD43_2: D43.2 T48.3(D)
NetD44_1: D44.1 R1081.1
NetD44_2: D44.2 T49.3(D)
NetR916_2: R916.2 R1059.1 T2.1(G)
NetR1082_2: R1082.2 R1089.1 T39.1(G)

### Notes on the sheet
- STAGE_7_8_9_SEQ
- (near T2) STAGE1
- (near T4) STAGE2
- SUPP_CLK
- (near T33) STAGE3
- (near T40) STAGE4
- (near T44) STAGE4
- (near T48) STAGE5

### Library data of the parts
D22 D25 D29-D44 = LTST-C190GKT: LED,  LTST-C190GKT; Manufacturer 1: Vishay Lite-On; Color: Green; Lens Color: Colorless; Luminous Intensity: 6mcd; Viewing Angle: 130°; Lens Style: Clear,Diffused,Colorless,Rectangular; Power Rating: 100mW; Dominant Wavelength: 569nm; Test Current: 10mA; Lens Transparency: Clear; Number of Elements: 1; Wavelength: 565nm; Voltage: 2V; Reverse Voltage: 5V
R913-R915 R917 R1060-R1066 R1069 R1070 R1075 R1076 R1078 R1079 R1081 = Resistor: KOA SPEAR ELECTRONICS - RK73H1JTTD1000F - RES, 100R, 1%, 0.1W, 0603, THICK FILM; Manufacturer: KOA Speer; Voltage Rating: 50V; Temperature Coefficient: 100ppm/°C
R916 R1082 = Resistor: Manufacturer 1: Yageo; Manufacturer Part Number 1: RC0402FR-0710KL; Tolerance: 1%; Temperature Coefficient: 100ppm/°C; Voltage Rating: 50V; Power Rating: 62.5mW
R1059 R1089 = Resistor: as R676 on sheet TPS7A88_3V3_1V8_0V9V@2x1A
T2-T4 T32 T33 T37-T49 = SI2342DS-T1-GE3: Trans MOSFET N-CH 8V 6A 3-Pin SOT-23 T/R; Manufacturer: Vishay; Rds On Max: 17mR; Input Capacitance: 1.07nF; Rise Time: 14ns; Max Power Dissipation: 2.5W; Number of Elements: 1; Power Dissipation: 1.3W; Turn-On Delay Time: 6ns; Turn-Off Delay Time: 65ns; Fall Time: 25ns; Threshold Voltage: 800mV; Gate to Source Voltage (Vgs): 5V

## Sheet Translator_I2C.SchDoc
size A3
Used 4 times, as channels Trans_LS_I2C0, Trans_PS_I2C0, Trans_PS_I2C1, Trans_LS_I2C1. Parts and nets are listed once, with the designators drawn on the sheet.
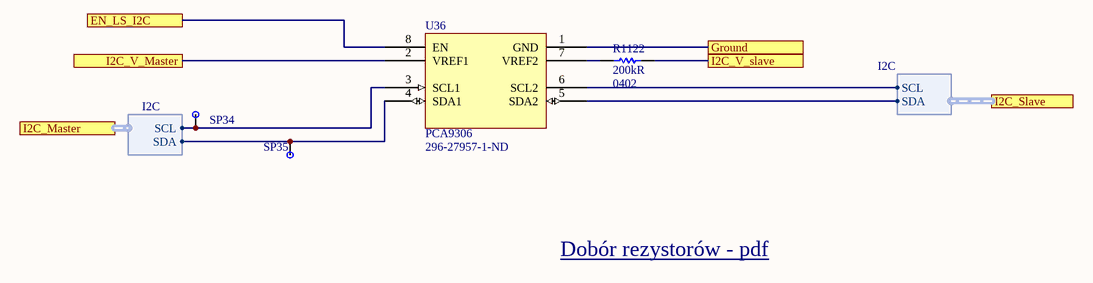
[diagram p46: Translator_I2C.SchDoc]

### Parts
R1122  200kR  Case/Package: 0402  [RES 0402/1005 RF KK]
SP34  SP  [MeasureTP]  (value not drawn)
SP35  SP  [MeasureTP]  (value not drawn)
U36  PCA9306  Supplier Part Number 1: 296-27957-1-ND  [PCA9306]

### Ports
EN_LS_I2C, Ground, I2C_Master (harness I2C), I2C_Slave (harness I2C), I2C_V_Master, I2C_V_slave

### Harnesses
I2C: SDA, SCL
I2C: SCL, SDA

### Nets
EN_LS_I2C: U36.8(EN) ; port EN_LS_I2C
Ground: U36.1(GND) ; port Ground
I2C_V_Master: U36.2(VREF1) ; port I2C_V_Master
I2C_V_slave: R1122.1 ; port I2C_V_slave
NetR1122_2: R1122.2 U36.7(VREF2)
NetSP34_1: SP34.1 U36.3(SCL1) ; port I2C_Master.SCL
NetSP35_1: SP35.1 U36.4(SDA1) ; port I2C_Master.SDA
NetU36_5: U36.5(SDA2) ; port I2C_Slave.SDA
NetU36_6: U36.6(SCL2) ; port I2C_Slave.SCL

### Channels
Trans_LS_I2C0: designators end in _Trans_LS_I2C0; ports EN_LS_I2C=NetR918_2 Ground=B503_Ground I2C_V_Master=US+_MGTVccAux I2C_V_slave=3V3_RAIL
Trans_PS_I2C0: designators end in _Trans_PS_I2C0; ports EN_LS_I2C=MIO_GPIO_2_75 Ground=B503_Ground I2C_V_Master=3V3_RAIL I2C_V_slave=3V3_RAIL
Trans_PS_I2C1: designators end in _Trans_PS_I2C1; ports EN_LS_I2C=MIO_GPIO_2_74 Ground=B503_Ground I2C_V_Master=ETH_VDDIO I2C_V_slave=3V3_RAIL
Trans_LS_I2C1: designators end in _Trans_LS_I2C1; ports EN_LS_I2C=NetR919_2 Ground=B503_Ground I2C_V_Master=US+_MGTVccAux I2C_V_slave=3V3_RAIL

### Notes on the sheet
- Dobór rezystorów - pdf <http://www.ti.com/lit/an/slva689/slva689.pdf>

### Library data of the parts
R1122 = Resistor: Manufacturer: Vishay BCcomponents; Manufacturer Part Number: MCS04020C2003FE000; Tolerance: 1%; Temperature Coefficient: 50ppm/°C
U36 = PCA9306: I2C [V] Level translator; Manufacturer: Texas Instruments; Manufacturer Part Number: PCA9306DQER; Max Supply Voltage: 5V; Min Supply Voltage: 0uV; Propagation Delay: 0.3ns; Number of Channels: 2; Turn-On Delay Time: 1.4ns; Low Level Output Current: 128mA

## Sheet GPIO_I2C.SchDoc: GPIO - EXPANDER
size A3; Organization: Altium Limited; Address1: L3, 12a Rodborough Rd; Address2: Frenchs Forest; Address3: NSW; Address4: Australia 2086
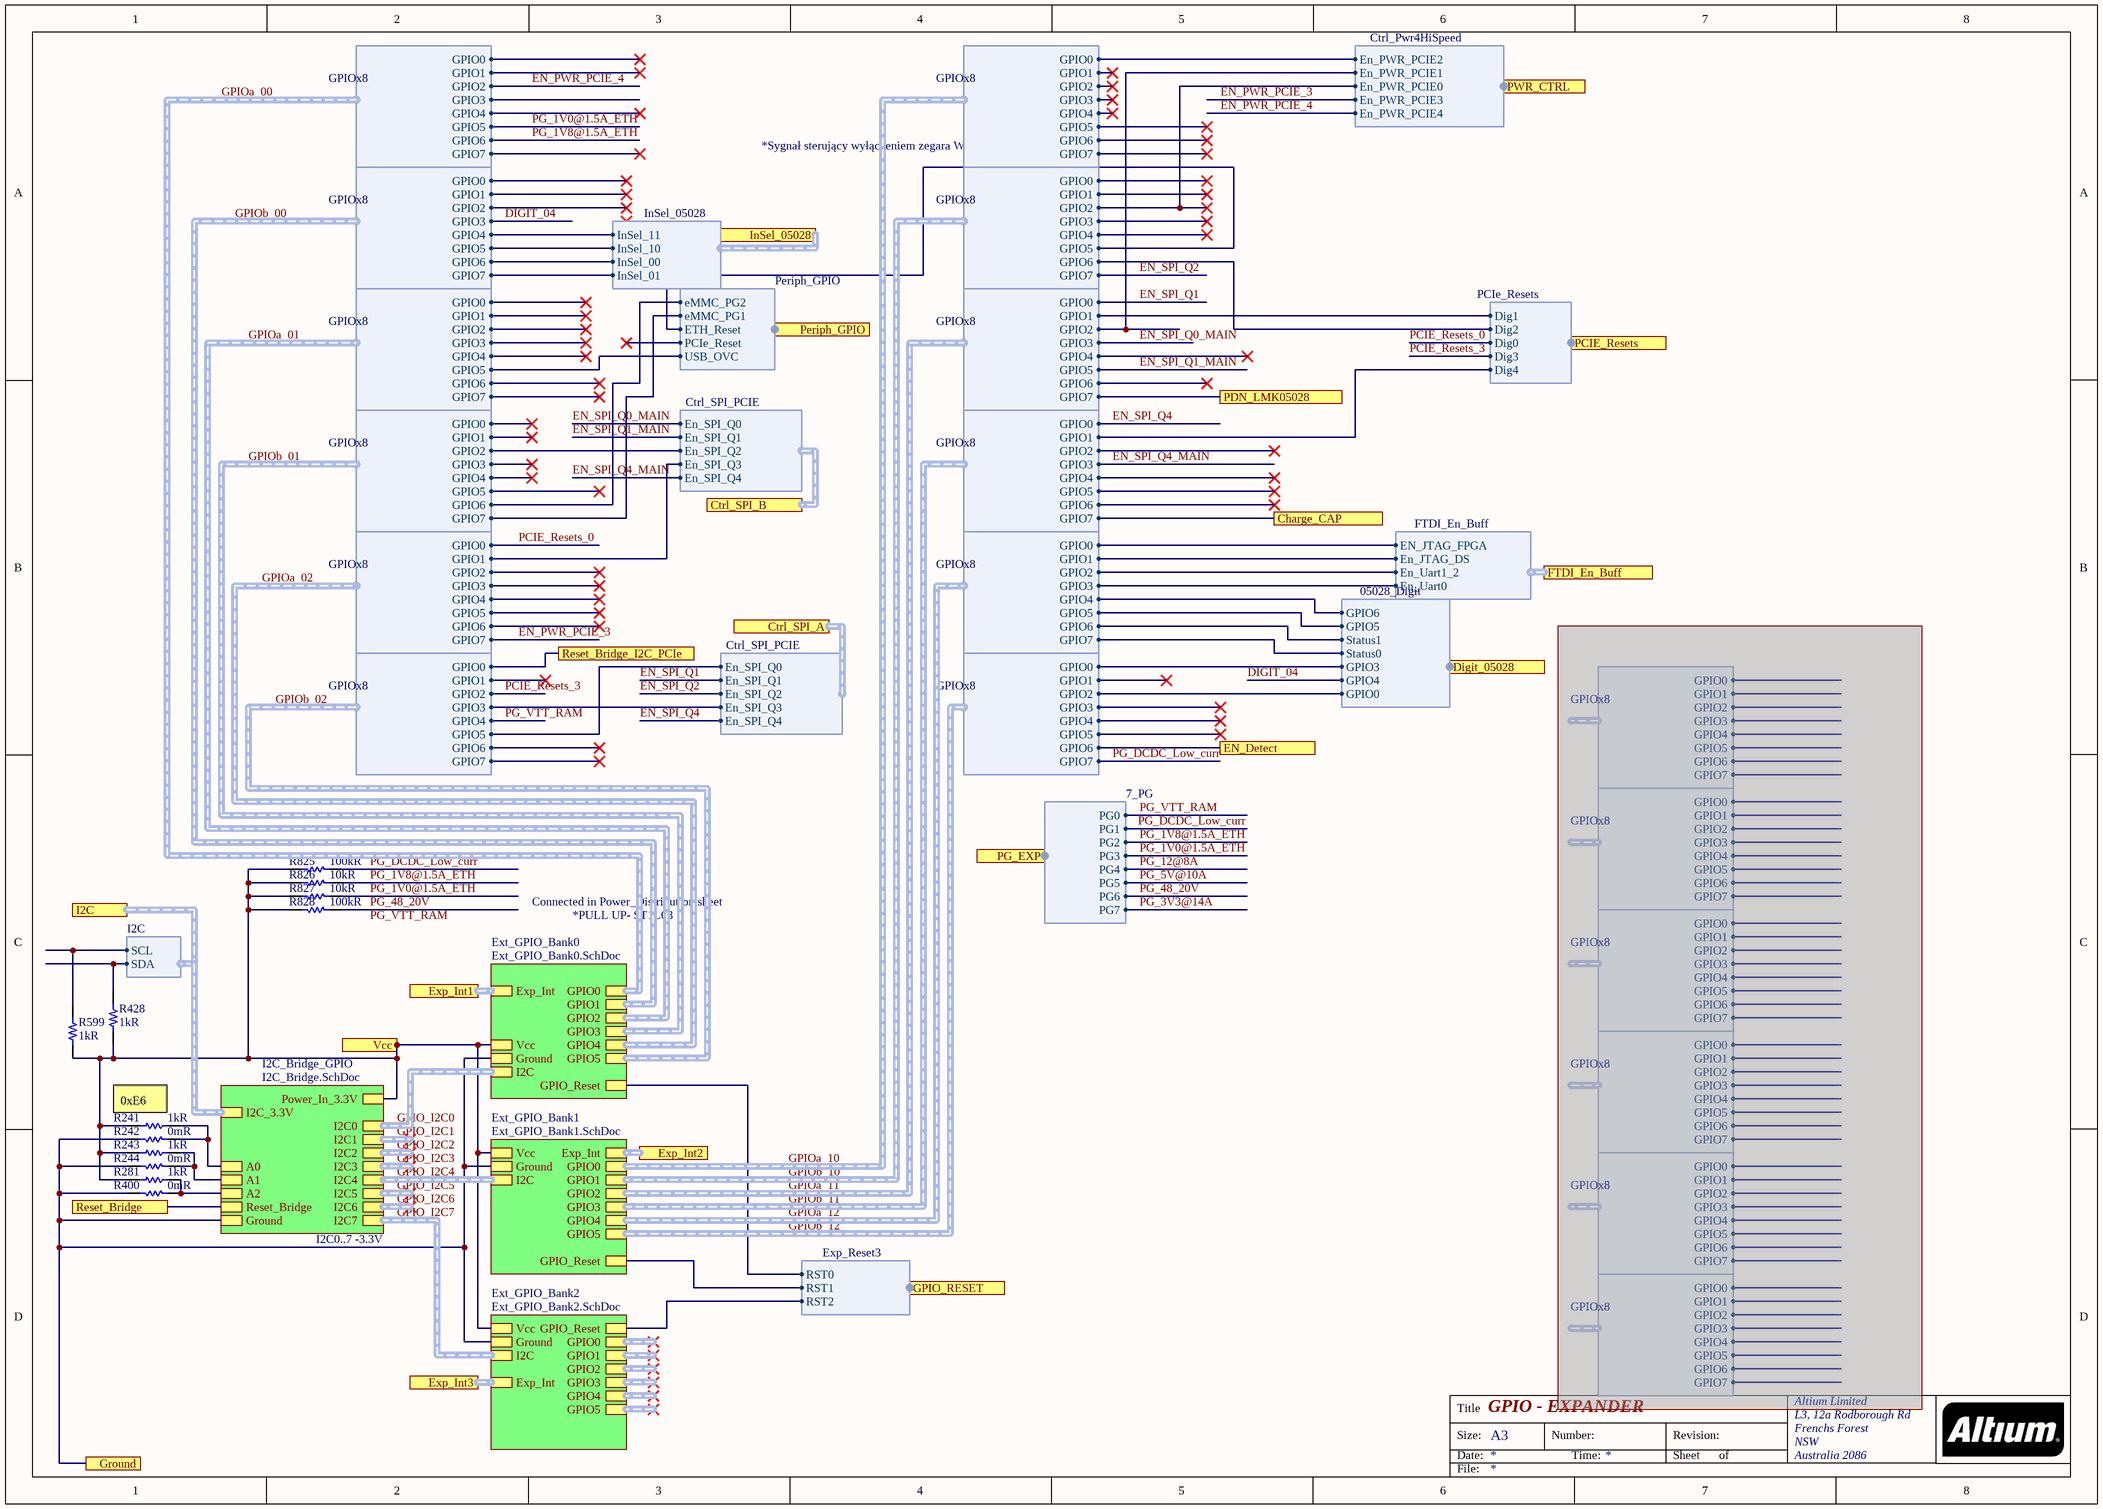
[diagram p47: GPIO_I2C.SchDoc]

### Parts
R241  1kR  [RES 0402/1005 RF KK]
R242  0mR  [RES 0402/1005 RF KK]
R243  1kR  [RES 0402/1005 RF KK]
R244  0mR  [RES 0402/1005 RF KK]
R281  1kR  [RES 0402/1005 RF KK]
R400  0mR  [RES 0402/1005 RF KK]
R428  1kR  [RES 0402/1005 RF KK]
R599  1kR  [RES 0402/1005 RF KK]
R825  100kR  [RES 0402/1005 RF KK]
R826  10kR  [RES 0402/1005 RF KK]
R827  10kR  [RES 0402/1005 RF KK]
R828  100kR  [RES 0402/1005 RF KK]

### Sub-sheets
Ext_GPIO_Bank0 = Ext_GPIO_Bank0.SchDoc: Vcc, Ground, I2C (harness I2C), GPIO5 (harness GPIOx8), GPIO4 (harness GPIOx8), GPIO3 (harness GPIOx8), GPIO2 (harness GPIOx8), GPIO1 (harness GPIOx8), GPIO0 (harness GPIOx8), GPIO_Reset, Exp_Int (harness Exp_Int)
Ext_GPIO_Bank1 = Ext_GPIO_Bank1.SchDoc: Vcc, Ground, I2C (harness I2C), GPIO5 (harness GPIOx8), GPIO4 (harness GPIOx8), GPIO3 (harness GPIOx8), GPIO2 (harness GPIOx8), GPIO1 (harness GPIOx8), GPIO0 (harness GPIOx8), GPIO_Reset, Exp_Int (harness Exp_Int)
Ext_GPIO_Bank2 = Ext_GPIO_Bank2.SchDoc: Vcc, Ground, I2C (harness I2C), GPIO5 (harness GPIOx8), GPIO4 (harness GPIOx8), GPIO3 (harness GPIOx8), GPIO2 (harness GPIOx8), GPIO1 (harness GPIOx8), GPIO0 (harness GPIOx8), GPIO_Reset, Exp_Int (harness Exp_Int)
I2C_Bridge_GPIO = I2C_Bridge.SchDoc: I2C0 (harness I2C), I2C1 (harness I2C), I2C2 (harness I2C), I2C3 (harness I2C), I2C4 (harness I2C), I2C5 (harness I2C), I2C6 (harness I2C), I2C7 (harness I2C), Ground, A2, A1, A0, I2C_3.3V (harness I2C), Reset_Bridge, Power_In_3.3V

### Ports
Charge_CAP, Ctrl_SPI_A (harness Ctrl_SPI_PCIE), Ctrl_SPI_B (harness Ctrl_SPI_PCIE), Digit_05028 (harness 05028_Digit), EN_Detect, Exp_Int1 (harness Exp_Int), Exp_Int2 (harness Exp_Int), Exp_Int3 (harness Exp_Int), FTDI_En_Buff (harness FTDI_En_Buff), GPIO_RESET (harness Exp_Reset3), Ground, I2C (harness I2C), InSel_05028 (harness InSel_05028), PCIE_Resets (harness PCIe_Resets), PDN_LMK05028, Periph_GPIO (harness Periph_GPIO), PG_EXP (harness 7_PG), PWR_CTRL (harness Ctrl_Pwr4HiSpeed), Reset_Bridge, Reset_Bridge_I2C_PCIe, Vcc

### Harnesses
Ctrl_SPI_PCIE: En_SPI_Q0, En_SPI_Q1, En_SPI_Q2, En_SPI_Q3, En_SPI_Q4
I2C: SCL, SDA
7_PG: PG0, PG1, PG2, PG3, PG4, PG5, PG6, PG7
GPIOx8: GPIO0, GPIO1, GPIO2, GPIO3, GPIO4, GPIO5, GPIO6, GPIO7
PCIe_Resets: Dig0, Dig1, Dig2, Dig3, Dig4
Ctrl_Pwr4HiSpeed: En_PWR_PCIE0, En_PWR_PCIE1, En_PWR_PCIE2, En_PWR_PCIE3, En_PWR_PCIE4
Exp_Reset3: RST0, RST1, RST2
InSel_05028: InSel_00, InSel_01, InSel_10, InSel_11
FTDI_En_Buff: EN_JTAG_FPGA, En_JTAG_DS, En_Uart1_2, En_Uart0
Periph_GPIO: eMMC_PG2, eMMC_PG1, ETH_Reset, PCIe_Reset, USB_OVC
05028_Digit: GPIO4, GPIO3, Status0, GPIO6, Status1, GPIO5, GPIO0

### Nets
B503_Ground: R242.2 R244.2 R400.2 ; port Ground, sheet I2C_Bridge_GPIO/Ground, sheet Ext_GPIO_Bank0/Ground, sheet Ext_GPIO_Bank1/Ground, sheet Ext_GPIO_Bank2/Ground
3V3_RAIL: R241.1 R243.1 R281.1 R428.2 R599.2 R825.1 R826.1 R827.1 R828.1 ; port Vcc, sheet I2C_Bridge_GPIO/Power_In_3.3V, sheet Ext_GPIO_Bank0/Vcc, sheet Ext_GPIO_Bank1/Vcc, sheet Ext_GPIO_Bank2/Vcc
Charge_CAP: port Charge_CAP, sheet Ext_GPIO_Bank1/GPIO3.GPIO7
D_05028_G3: sheet Ext_GPIO_Bank1/GPIO5.GPIO0, port Digit_05028.GPIO3
D_05028_G5: sheet Ext_GPIO_Bank1/GPIO4.GPIO5, port Digit_05028.GPIO5
D_05028_G6: sheet Ext_GPIO_Bank1/GPIO4.GPIO4, port Digit_05028.GPIO6
D_05028_S0: sheet Ext_GPIO_Bank1/GPIO4.GPIO7, port Digit_05028.Status0
D_05028_S1: sheet Ext_GPIO_Bank1/GPIO4.GPIO6, port Digit_05028.Status1
DIGIT_04: sheet Ext_GPIO_Bank0/GPIO1.GPIO3, port Digit_05028.GPIO4  [project net D_05028_G4]
eMMC_PG1: sheet Ext_GPIO_Bank0/GPIO3.GPIO7, port Periph_GPIO.eMMC_PG1
eMMC_PG2: sheet Ext_GPIO_Bank0/GPIO3.GPIO6, port Periph_GPIO.eMMC_PG2
EN_Detect: port EN_Detect, sheet Ext_GPIO_Bank1/GPIO5.GPIO6
EN_PWR_PCIE_3: sheet Ext_GPIO_Bank0/GPIO4.GPIO7, port PWR_CTRL.En_PWR_PCIE3
EN_PWR_PCIE_4: sheet Ext_GPIO_Bank0/GPIO0.GPIO2, port PWR_CTRL.En_PWR_PCIE4
En_PWRSwitch_PCIE0: sheet Ext_GPIO_Bank1/GPIO1.GPIO2, port PWR_CTRL.En_PWR_PCIE0
En_PWRSwitch_PCIE1: sheet Ext_GPIO_Bank1/GPIO2.GPIO2, port PWR_CTRL.En_PWR_PCIE1
En_PWRSwitch_PCIE2: sheet Ext_GPIO_Bank1/GPIO0.GPIO0, port PWR_CTRL.En_PWR_PCIE2
EN_SPI_Q0_MAIN: port Ctrl_SPI_B.En_SPI_Q0, sheet Ext_GPIO_Bank1/GPIO2.GPIO3
EN_SPI_Q1: port Ctrl_SPI_A.En_SPI_Q1, sheet Ext_GPIO_Bank1/GPIO2.GPIO0
EN_SPI_Q1_MAIN: port Ctrl_SPI_B.En_SPI_Q1, sheet Ext_GPIO_Bank1/GPIO2.GPIO5
EN_SPI_Q2: port Ctrl_SPI_A.En_SPI_Q2, sheet Ext_GPIO_Bank1/GPIO1.GPIO7
EN_SPI_Q4: port Ctrl_SPI_A.En_SPI_Q4, sheet Ext_GPIO_Bank1/GPIO3.GPIO0
EN_SPI_Q4_MAIN: port Ctrl_SPI_B.En_SPI_Q4, sheet Ext_GPIO_Bank1/GPIO3.GPIO3
FTDI_JTAG_ON_1: sheet Ext_GPIO_Bank1/GPIO4.GPIO0, port FTDI_En_Buff.EN_JTAG_FPGA
FTDI_JTAG_ON_2: sheet Ext_GPIO_Bank1/GPIO4.GPIO1, port FTDI_En_Buff.En_JTAG_DS
FTDI_JTAG_ON_3: sheet Ext_GPIO_Bank1/GPIO4.GPIO2, port FTDI_En_Buff.En_Uart1_2
FTDI_JTAG_ON_4: sheet Ext_GPIO_Bank1/GPIO4.GPIO3, port FTDI_En_Buff.En_Uart0
GPIO_ETH_EXPANDER: sheet Ext_GPIO_Bank1/GPIO1.GPIO5, port Periph_GPIO.ETH_Reset
GPIO_Exp_Reset0: sheet Ext_GPIO_Bank0/GPIO_Reset, port GPIO_RESET.RST0
GPIO_Exp_Reset1: sheet Ext_GPIO_Bank1/GPIO_Reset, port GPIO_RESET.RST1
GPIO_Exp_Reset2: sheet Ext_GPIO_Bank2/GPIO_Reset, port GPIO_RESET.RST2
GPIOa_01.GPIO5: sheet Ext_GPIO_Bank0/GPIO2.GPIO5, port Periph_GPIO.USB_OVC
GPIOa_02.GPIO1: port Ctrl_SPI_B.En_SPI_Q3, sheet Ext_GPIO_Bank0/GPIO4.GPIO1
GPIOa_11.GPIO1: sheet Ext_GPIO_Bank1/GPIO2.GPIO1, port PCIE_Resets.Dig1
GPIOa_11.GPIO7: port PDN_LMK05028, sheet Ext_GPIO_Bank1/GPIO2.GPIO7
GPIOb_00.GPIO4: sheet Ext_GPIO_Bank0/GPIO1.GPIO4, port InSel_05028.InSel_11
GPIOb_00.GPIO5: sheet Ext_GPIO_Bank0/GPIO1.GPIO5, port InSel_05028.InSel_10
GPIOb_00.GPIO6: sheet Ext_GPIO_Bank0/GPIO1.GPIO6, port InSel_05028.InSel_00
GPIOb_00.GPIO7: sheet Ext_GPIO_Bank0/GPIO1.GPIO7, port InSel_05028.InSel_01
GPIOb_01.GPIO2: port Ctrl_SPI_B.En_SPI_Q2, sheet Ext_GPIO_Bank0/GPIO3.GPIO2
GPIOb_02.GPIO0: port Reset_Bridge_I2C_PCIe, sheet Ext_GPIO_Bank0/GPIO5.GPIO0
GPIOb_02.GPIO3: port Ctrl_SPI_A.En_SPI_Q3, sheet Ext_GPIO_Bank0/GPIO5.GPIO3
GPIOb_02.GPIO5: port Ctrl_SPI_A.En_SPI_Q0, sheet Ext_GPIO_Bank0/GPIO5.GPIO5
GPIOb_10.GPIO6: sheet Ext_GPIO_Bank1/GPIO1.GPIO6, port PCIE_Resets.Dig2
GPIOb_11.GPIO1: sheet Ext_GPIO_Bank1/GPIO3.GPIO1, port PCIE_Resets.Dig4
GPIOb_12.GPIO2: sheet Ext_GPIO_Bank1/GPIO5.GPIO2, port Digit_05028.GPIO0
I2C1_Rail.SCL: R599.1 ; port I2C.SCL
I2C1_Rail.SDA: R428.1 ; port I2C.SDA
PCIE_Resets_0: sheet Ext_GPIO_Bank0/GPIO4.GPIO0, port PCIE_Resets.Dig0  [project net GPIOa_02.GPIO0]
PCIE_Resets_3: sheet Ext_GPIO_Bank0/GPIO5.GPIO2, port PCIE_Resets.Dig3  [project net GPIOb_02.GPIO2]
PG_1V0@1.5A_ETH: R827.2 ; port PG_EXP.PG3, sheet Ext_GPIO_Bank0/GPIO0.GPIO5  [project net GPIOa_00.GPIO5]
PG_1V8@1.5A_ETH: R826.2 ; port PG_EXP.PG2, sheet Ext_GPIO_Bank0/GPIO0.GPIO6  [project net GPIOa_00.GPIO6]
PG_48_20V: R828.2 ; port PG_EXP.PG6
PG_DCDC_Low_curr: R825.2 ; port PG_EXP.PG1, sheet Ext_GPIO_Bank1/GPIO5.GPIO7  [project net GPIOb_12.GPIO7]
PG_VTT_RAM: port PG_EXP.PG0, sheet Ext_GPIO_Bank0/GPIO5.GPIO4  [project net GPIOb_02.GPIO4]
NetR241_2: R241.2 R242.1 ; sheet I2C_Bridge_GPIO/A0
NetR243_2: R243.2 R244.1 ; sheet I2C_Bridge_GPIO/A1
NetR281_2: R281.2 R400.1 ; sheet I2C_Bridge_GPIO/A2
NetSP12_I2C_Bridge_GPIO_1: port Reset_Bridge, sheet I2C_Bridge_GPIO/Reset_Bridge

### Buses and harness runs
harness GPIO_I2C0 = sheet Ext_GPIO_Bank0/I2C = sheet I2C_Bridge_GPIO/I2C0
harness GPIO_I2C1 = sheet I2C_Bridge_GPIO/I2C1
harness GPIO_I2C2 = sheet I2C_Bridge_GPIO/I2C2
harness GPIO_I2C3 = sheet I2C_Bridge_GPIO/I2C3
harness GPIO_I2C4 = sheet Ext_GPIO_Bank1/I2C = sheet I2C_Bridge_GPIO/I2C4
harness GPIO_I2C5 = sheet I2C_Bridge_GPIO/I2C5
harness GPIO_I2C6 = sheet I2C_Bridge_GPIO/I2C6
harness GPIO_I2C7 = sheet Ext_GPIO_Bank2/I2C = sheet I2C_Bridge_GPIO/I2C7
harness GPIOa_00 = sheet Ext_GPIO_Bank0/GPIO0
harness GPIOa_01 = sheet Ext_GPIO_Bank0/GPIO2
harness GPIOa_02 = sheet Ext_GPIO_Bank0/GPIO4
harness GPIOa_10 = sheet Ext_GPIO_Bank1/GPIO0
harness GPIOa_11 = sheet Ext_GPIO_Bank1/GPIO2
harness GPIOa_12 = sheet Ext_GPIO_Bank1/GPIO4
harness GPIOb_00 = sheet Ext_GPIO_Bank0/GPIO1
harness GPIOb_01 = sheet Ext_GPIO_Bank0/GPIO3
harness GPIOb_02 = sheet Ext_GPIO_Bank0/GPIO5
harness GPIOb_10 = sheet Ext_GPIO_Bank1/GPIO1
harness GPIOb_11 = sheet Ext_GPIO_Bank1/GPIO3
harness GPIOb_12 = sheet Ext_GPIO_Bank1/GPIO5
harness port Exp_Int1 = sheet Ext_GPIO_Bank0/Exp_Int
harness port Exp_Int2 = sheet Ext_GPIO_Bank1/Exp_Int
harness port Exp_Int3 = sheet Ext_GPIO_Bank2/Exp_Int
harness port I2C = sheet I2C_Bridge_GPIO/I2C_3.3V

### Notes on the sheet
- *Sygnał sterujący wyłączeniem zegara WR
- Connected in Power_Distribution sheet
- *PULL UP- ST1L08
- (near R241) 0xE6
- I2C0..7 -3.3V
- Labels drawn without touching a wire or pin: PG_VTT_RAM

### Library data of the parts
R241 R243 R281 = Resistor: PANASONIC - ERJ-2RKF1001X - SMD Chip Resistor, 0402 [1005 Metric], 1 kohm, ERJ2R Series, 50 V, Thick Film, 100 mW; Voltage Rating (DC): 50V; Temperature Coefficient: 100ppm/°C; Tolerance: 1%; Power Rating: 100mW
R242 R244 R400 = Resistor: as R665 on sheet Power_48_20V@3A
R428 R599 = Resistor: Manufacturer: Panasonic; Manufacturer Part Number: ERJ-2RKF1001X; Tolerance: 1%; Power Rating: 100mW; Temperature Coefficient: 100ppm/°C; Voltage Rating: 50V
R825 R828 = Resistor: as R646 on sheet ADP1741_3V3_0V85
R826 R827 = Resistor: as R916 on sheet Power_LED

## Sheet Ext_GPIO_Bank0.SchDoc
size A3
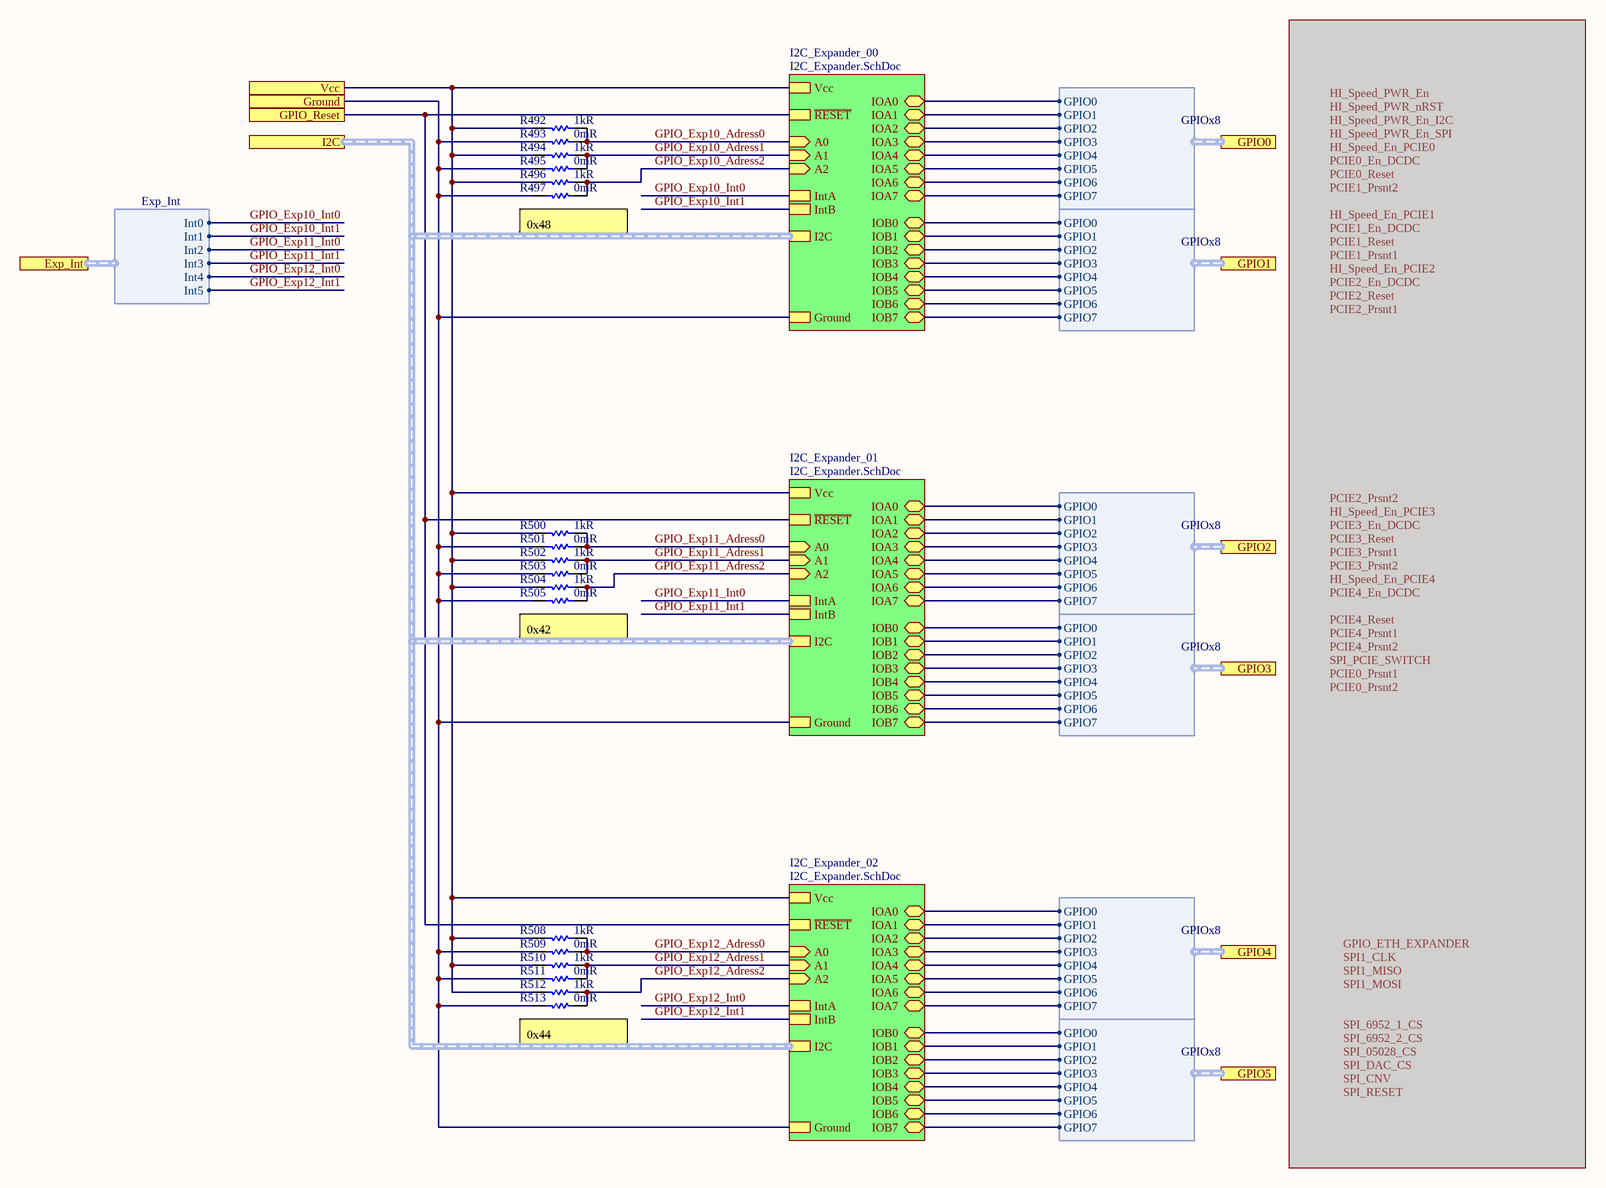
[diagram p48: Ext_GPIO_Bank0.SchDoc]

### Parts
R492  1kR  [RES 0402/1005 RF KK]
R493  0mR  [RES 0402/1005 RF KK]
R494  1kR  [RES 0402/1005 RF KK]
R495  0mR  [RES 0402/1005 RF KK]
R496  1kR  [RES 0402/1005 RF KK]
R497  0mR  [RES 0402/1005 RF KK]
R500  1kR  [RES 0402/1005 RF KK]
R501  0mR  [RES 0402/1005 RF KK]
R502  1kR  [RES 0402/1005 RF KK]
R503  0mR  [RES 0402/1005 RF KK]
R504  1kR  [RES 0402/1005 RF KK]
R505  0mR  [RES 0402/1005 RF KK]
R508  1kR  [RES 0402/1005 RF KK]
R509  0mR  [RES 0402/1005 RF KK]
R510  1kR  [RES 0402/1005 RF KK]
R511  0mR  [RES 0402/1005 RF KK]
R512  1kR  [RES 0402/1005 RF KK]
R513  0mR  [RES 0402/1005 RF KK]

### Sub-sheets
I2C_Expander_00 = I2C_Expander.SchDoc: IOA7 (bidir), IOA3 (bidir), IOA6 (bidir), IOA1 (bidir), IOA0 (bidir), IOA5 (bidir), IOB1 (bidir), IOB2 (bidir), IOB5 (bidir), IOB6 (bidir), IOB7 (bidir), IntA, IntB, Ground, IOB4 (bidir), IOB3 (bidir), IOA2 (bidir), IOA4 (bidir), IOB0 (bidir), Vcc, ~{RESET}, I2C (harness I2C), A2 (in), A1 (in), A0 (in)
I2C_Expander_01 = I2C_Expander.SchDoc: IOA7 (bidir), IOA3 (bidir), IOA6 (bidir), IOA1 (bidir), IOA0 (bidir), IOA5 (bidir), IOB1 (bidir), IOB2 (bidir), IOB5 (bidir), IOB6 (bidir), IOB7 (bidir), IntA, IntB, Ground, IOB4 (bidir), IOB3 (bidir), IOA2 (bidir), IOA4 (bidir), IOB0 (bidir), Vcc, ~{RESET}, I2C (harness I2C), A2 (in), A1 (in), A0 (in)
I2C_Expander_02 = I2C_Expander.SchDoc: IOA7 (bidir), IOA3 (bidir), IOA6 (bidir), IOA1 (bidir), IOA0 (bidir), IOA5 (bidir), IOB1 (bidir), IOB2 (bidir), IOB5 (bidir), IOB6 (bidir), IOB7 (bidir), IntA, IntB, Ground, IOB4 (bidir), IOB3 (bidir), IOA2 (bidir), IOA4 (bidir), IOB0 (bidir), Vcc, ~{RESET}, I2C (harness I2C), A2 (in), A1 (in), A0 (in)

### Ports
Exp_Int (harness Exp_Int), GPIO0 (harness GPIOx8), GPIO1 (harness GPIOx8), GPIO2 (harness GPIOx8), GPIO3 (harness GPIOx8), GPIO4 (harness GPIOx8), GPIO5 (harness GPIOx8), GPIO_Reset, Ground, I2C (harness I2C), Vcc

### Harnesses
GPIOx8: GPIO0, GPIO1, GPIO2, GPIO3, GPIO4, GPIO5, GPIO6, GPIO7
Exp_Int: Int0, Int1, Int2, Int3, Int4, Int5

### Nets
B503_Ground: R493.2 R495.2 R497.2 R501.2 R503.2 R505.2 R509.2 R511.2 R513.2 ; port Ground, sheet I2C_Expander_00/Ground, sheet I2C_Expander_01/Ground, sheet I2C_Expander_02/Ground
3V3_RAIL: R492.1 R494.1 R496.1 R500.1 R502.1 R504.1 R508.1 R510.1 R512.1 ; port Vcc, sheet I2C_Expander_00/Vcc, sheet I2C_Expander_01/Vcc, sheet I2C_Expander_02/Vcc
D_05028_G4: sheet I2C_Expander_00/IOB3, port GPIO1.GPIO3
eMMC_PG1: sheet I2C_Expander_01/IOB7, port GPIO3.GPIO7
eMMC_PG2: sheet I2C_Expander_01/IOB6, port GPIO3.GPIO6
EN_PWR_PCIE_3: sheet I2C_Expander_02/IOA7, port GPIO4.GPIO7
EN_PWR_PCIE_4: sheet I2C_Expander_00/IOA2, port GPIO0.GPIO2
GPIO_Exp10_Adress0: R492.2 R493.1 ; sheet I2C_Expander_00/A0
GPIO_Exp10_Adress1: R494.2 R495.1 ; sheet I2C_Expander_00/A1
GPIO_Exp10_Adress2: R496.2 R497.1 ; sheet I2C_Expander_00/A2
GPIO_Exp10_Int0: sheet I2C_Expander_00/IntA, port Exp_Int.Int0
GPIO_Exp10_Int1: sheet I2C_Expander_00/IntB, port Exp_Int.Int1
GPIO_Exp11_Adress0: R500.2 R501.1 ; sheet I2C_Expander_01/A0
GPIO_Exp11_Adress1: R502.2 R503.1 ; sheet I2C_Expander_01/A1
GPIO_Exp11_Adress2: R504.2 R505.1 ; sheet I2C_Expander_01/A2
GPIO_Exp11_Int0: sheet I2C_Expander_01/IntA, port Exp_Int.Int2
GPIO_Exp11_Int1: sheet I2C_Expander_01/IntB, port Exp_Int.Int3
GPIO_Exp12_Adress0: R508.2 R509.1 ; sheet I2C_Expander_02/A0
GPIO_Exp12_Adress1: R510.2 R511.1 ; sheet I2C_Expander_02/A1
GPIO_Exp12_Adress2: R512.2 R513.1 ; sheet I2C_Expander_02/A2
GPIO_Exp12_Int0: sheet I2C_Expander_02/IntA, port Exp_Int.Int4
GPIO_Exp12_Int1: sheet I2C_Expander_02/IntB, port Exp_Int.Int5
GPIO_Exp_Reset0: port GPIO_Reset, sheet I2C_Expander_00/~{RESET}, sheet I2C_Expander_01/~{RESET}, sheet I2C_Expander_02/~{RESET}
GPIOa_00.GPIO0: sheet I2C_Expander_00/IOA0, port GPIO0.GPIO0
GPIOa_00.GPIO1: sheet I2C_Expander_00/IOA1, port GPIO0.GPIO1
GPIOa_00.GPIO3: sheet I2C_Expander_00/IOA3, port GPIO0.GPIO3
GPIOa_00.GPIO4: sheet I2C_Expander_00/IOA4, port GPIO0.GPIO4
GPIOa_00.GPIO5: sheet I2C_Expander_00/IOA5, port GPIO0.GPIO5
GPIOa_00.GPIO6: sheet I2C_Expander_00/IOA6, port GPIO0.GPIO6
GPIOa_00.GPIO7: sheet I2C_Expander_00/IOA7, port GPIO0.GPIO7
GPIOa_01.GPIO0: sheet I2C_Expander_01/IOA0, port GPIO2.GPIO0
GPIOa_01.GPIO1: sheet I2C_Expander_01/IOA1, port GPIO2.GPIO1
GPIOa_01.GPIO2: sheet I2C_Expander_01/IOA2, port GPIO2.GPIO2
GPIOa_01.GPIO3: sheet I2C_Expander_01/IOA3, port GPIO2.GPIO3
GPIOa_01.GPIO4: sheet I2C_Expander_01/IOA4, port GPIO2.GPIO4
GPIOa_01.GPIO5: sheet I2C_Expander_01/IOA5, port GPIO2.GPIO5
GPIOa_01.GPIO6: sheet I2C_Expander_01/IOA6, port GPIO2.GPIO6
GPIOa_01.GPIO7: sheet I2C_Expander_01/IOA7, port GPIO2.GPIO7
GPIOa_02.GPIO0: sheet I2C_Expander_02/IOA0, port GPIO4.GPIO0
GPIOa_02.GPIO1: sheet I2C_Expander_02/IOA1, port GPIO4.GPIO1
GPIOa_02.GPIO2: sheet I2C_Expander_02/IOA2, port GPIO4.GPIO2
GPIOa_02.GPIO3: sheet I2C_Expander_02/IOA3, port GPIO4.GPIO3
GPIOa_02.GPIO4: sheet I2C_Expander_02/IOA4, port GPIO4.GPIO4
GPIOa_02.GPIO5: sheet I2C_Expander_02/IOA5, port GPIO4.GPIO5
GPIOa_02.GPIO6: sheet I2C_Expander_02/IOA6, port GPIO4.GPIO6
GPIOb_00.GPIO0: sheet I2C_Expander_00/IOB0, port GPIO1.GPIO0
GPIOb_00.GPIO1: sheet I2C_Expander_00/IOB1, port GPIO1.GPIO1
GPIOb_00.GPIO2: sheet I2C_Expander_00/IOB2, port GPIO1.GPIO2
GPIOb_00.GPIO4: sheet I2C_Expander_00/IOB4, port GPIO1.GPIO4
GPIOb_00.GPIO5: sheet I2C_Expander_00/IOB5, port GPIO1.GPIO5
GPIOb_00.GPIO6: sheet I2C_Expander_00/IOB6, port GPIO1.GPIO6
GPIOb_00.GPIO7: sheet I2C_Expander_00/IOB7, port GPIO1.GPIO7
GPIOb_01.GPIO0: sheet I2C_Expander_01/IOB0, port GPIO3.GPIO0
GPIOb_01.GPIO1: sheet I2C_Expander_01/IOB1, port GPIO3.GPIO1
GPIOb_01.GPIO2: sheet I2C_Expander_01/IOB2, port GPIO3.GPIO2
GPIOb_01.GPIO3: sheet I2C_Expander_01/IOB3, port GPIO3.GPIO3
GPIOb_01.GPIO4: sheet I2C_Expander_01/IOB4, port GPIO3.GPIO4
GPIOb_01.GPIO5: sheet I2C_Expander_01/IOB5, port GPIO3.GPIO5
GPIOb_02.GPIO0: sheet I2C_Expander_02/IOB0, port GPIO5.GPIO0
GPIOb_02.GPIO1: sheet I2C_Expander_02/IOB1, port GPIO5.GPIO1
GPIOb_02.GPIO2: sheet I2C_Expander_02/IOB2, port GPIO5.GPIO2
GPIOb_02.GPIO3: sheet I2C_Expander_02/IOB3, port GPIO5.GPIO3
GPIOb_02.GPIO4: sheet I2C_Expander_02/IOB4, port GPIO5.GPIO4
GPIOb_02.GPIO5: sheet I2C_Expander_02/IOB5, port GPIO5.GPIO5
GPIOb_02.GPIO6: sheet I2C_Expander_02/IOB6, port GPIO5.GPIO6
GPIOb_02.GPIO7: sheet I2C_Expander_02/IOB7, port GPIO5.GPIO7

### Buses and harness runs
harness port I2C = sheet I2C_Expander_00/I2C = sheet I2C_Expander_01/I2C = sheet I2C_Expander_02/I2C

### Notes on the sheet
- (near R497) 0x48
- (near R505) 0x42
- (near R513) 0x44

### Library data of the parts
R492 R494 R496 R500 R502 R504 R508 R510 R512 = Resistor: PANASONIC - ERJ-2RKF1001X - SMD Chip Resistor, 0402 [1005 Metric], 1 kohm, ERJ2R Series, 50 V, Thick Film, 100 mW; Temperature Coefficient: 100ppm/°C; Tolerance: 1%; Voltage Rating (DC): 50V; Power Rating: 100mW
R493 R495 R497 R501 R503 R505 R509 R511 R513 = Resistor: as R665 on sheet Power_48_20V@3A

## Sheet Ext_GPIO_Bank1.SchDoc
size A3
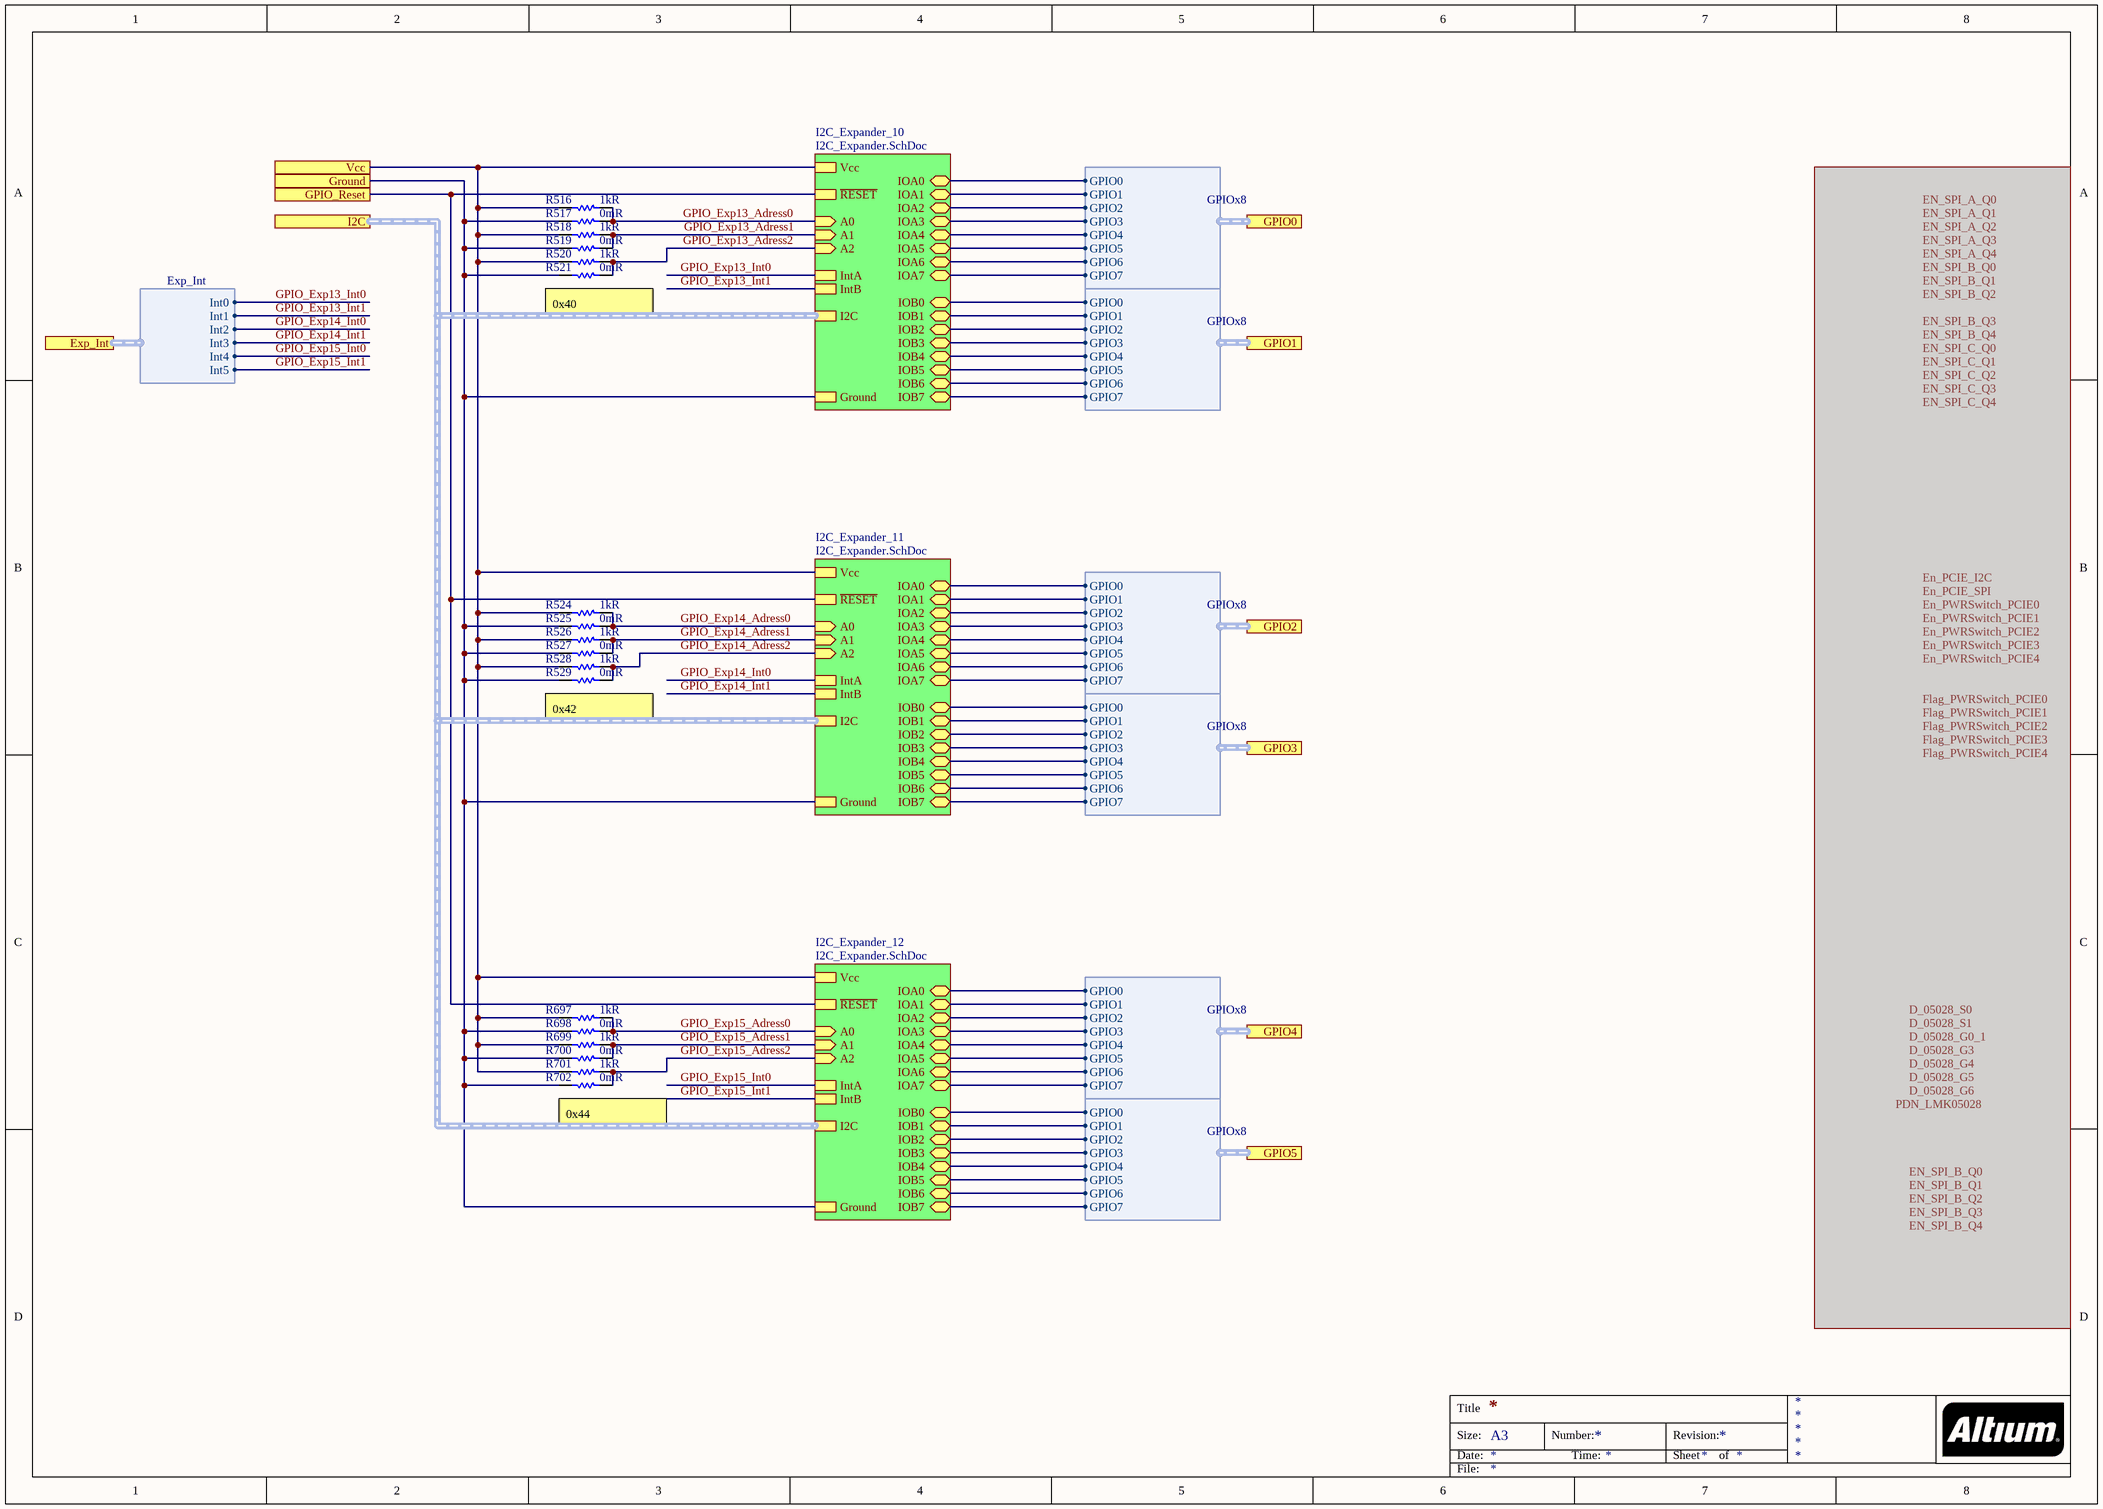
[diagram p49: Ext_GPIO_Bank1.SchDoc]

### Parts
R516  1kR  [RES 0402/1005 RF KK]
R517  0mR  [RES 0402/1005 RF KK]
R518  1kR  [RES 0402/1005 RF KK]
R519  0mR  [RES 0402/1005 RF KK]
R520  1kR  [RES 0402/1005 RF KK]
R521  0mR  [RES 0402/1005 RF KK]
R524  1kR  [RES 0402/1005 RF KK]
R525  0mR  [RES 0402/1005 RF KK]
R526  1kR  [RES 0402/1005 RF KK]
R527  0mR  [RES 0402/1005 RF KK]
R528  1kR  [RES 0402/1005 RF KK]
R529  0mR  [RES 0402/1005 RF KK]
R697  1kR  [RES 0402/1005 RF KK]
R698  0mR  [RES 0402/1005 RF KK]
R699  1kR  [RES 0402/1005 RF KK]
R700  0mR  [RES 0402/1005 RF KK]
R701  1kR  [RES 0402/1005 RF KK]
R702  0mR  [RES 0402/1005 RF KK]

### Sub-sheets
I2C_Expander_10 = I2C_Expander.SchDoc: IOA7 (bidir), IOA3 (bidir), IOA6 (bidir), IOA1 (bidir), IOA0 (bidir), IOA5 (bidir), IOB1 (bidir), IOB2 (bidir), IOB5 (bidir), IOB6 (bidir), IOB7 (bidir), IntA, IntB, Ground, IOB4 (bidir), IOB3 (bidir), IOA2 (bidir), IOA4 (bidir), IOB0 (bidir), Vcc, ~{RESET}, I2C (harness I2C), A2 (in), A1 (in), A0 (in)
I2C_Expander_11 = I2C_Expander.SchDoc: IOA7 (bidir), IOA3 (bidir), IOA6 (bidir), IOA1 (bidir), IOA0 (bidir), IOA5 (bidir), IOB1 (bidir), IOB2 (bidir), IOB5 (bidir), IOB6 (bidir), IOB7 (bidir), IntA, IntB, Ground, IOB4 (bidir), IOB3 (bidir), IOA2 (bidir), IOA4 (bidir), IOB0 (bidir), Vcc, ~{RESET}, I2C (harness I2C), A2 (in), A1 (in), A0 (in)
I2C_Expander_12 = I2C_Expander.SchDoc: IOA7 (bidir), IOA3 (bidir), IOA6 (bidir), IOA1 (bidir), IOA0 (bidir), IOA5 (bidir), IOB1 (bidir), IOB2 (bidir), IOB5 (bidir), IOB6 (bidir), IOB7 (bidir), IntA, IntB, Ground, IOB4 (bidir), IOB3 (bidir), IOA2 (bidir), IOA4 (bidir), IOB0 (bidir), Vcc, ~{RESET}, I2C (harness I2C), A2 (in), A1 (in), A0 (in)

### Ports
Exp_Int (harness Exp_Int), GPIO0 (harness GPIOx8), GPIO1 (harness GPIOx8), GPIO2 (harness GPIOx8), GPIO3 (harness GPIOx8), GPIO4 (harness GPIOx8), GPIO5 (harness GPIOx8), GPIO_Reset, Ground, I2C (harness I2C), Vcc

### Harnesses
GPIOx8: GPIO0, GPIO1, GPIO2, GPIO3, GPIO4, GPIO5, GPIO6, GPIO7
Exp_Int: Int0, Int1, Int2, Int3, Int4, Int5

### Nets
B503_Ground: R517.2 R519.2 R521.2 R525.2 R527.2 R529.2 R698.2 R700.2 R702.2 ; port Ground, sheet I2C_Expander_10/Ground, sheet I2C_Expander_11/Ground, sheet I2C_Expander_12/Ground
3V3_RAIL: R516.1 R518.1 R520.1 R524.1 R526.1 R528.1 R697.1 R699.1 R701.1 ; port Vcc, sheet I2C_Expander_10/Vcc, sheet I2C_Expander_11/Vcc, sheet I2C_Expander_12/Vcc
Charge_CAP: sheet I2C_Expander_11/IOB7, port GPIO3.GPIO7
D_05028_G3: sheet I2C_Expander_12/IOB0, port GPIO5.GPIO0
D_05028_G5: sheet I2C_Expander_12/IOA5, port GPIO4.GPIO5
D_05028_G6: sheet I2C_Expander_12/IOA4, port GPIO4.GPIO4
D_05028_S0: sheet I2C_Expander_12/IOA7, port GPIO4.GPIO7
D_05028_S1: sheet I2C_Expander_12/IOA6, port GPIO4.GPIO6
EN_Detect: sheet I2C_Expander_12/IOB6, port GPIO5.GPIO6
En_PWRSwitch_PCIE0: sheet I2C_Expander_10/IOB2, port GPIO1.GPIO2
En_PWRSwitch_PCIE1: sheet I2C_Expander_11/IOA2, port GPIO2.GPIO2
En_PWRSwitch_PCIE2: sheet I2C_Expander_10/IOA0, port GPIO0.GPIO0
EN_SPI_Q0_MAIN: sheet I2C_Expander_11/IOA3, port GPIO2.GPIO3
EN_SPI_Q1: sheet I2C_Expander_11/IOA0, port GPIO2.GPIO0
EN_SPI_Q1_MAIN: sheet I2C_Expander_11/IOA5, port GPIO2.GPIO5
EN_SPI_Q2: sheet I2C_Expander_10/IOB7, port GPIO1.GPIO7
EN_SPI_Q4: sheet I2C_Expander_11/IOB0, port GPIO3.GPIO0
EN_SPI_Q4_MAIN: sheet I2C_Expander_11/IOB3, port GPIO3.GPIO3
FTDI_JTAG_ON_1: sheet I2C_Expander_12/IOA0, port GPIO4.GPIO0
FTDI_JTAG_ON_2: sheet I2C_Expander_12/IOA1, port GPIO4.GPIO1
FTDI_JTAG_ON_3: sheet I2C_Expander_12/IOA2, port GPIO4.GPIO2
FTDI_JTAG_ON_4: sheet I2C_Expander_12/IOA3, port GPIO4.GPIO3
GPIO_ETH_EXPANDER: sheet I2C_Expander_10/IOB5, port GPIO1.GPIO5
GPIO_Exp13_Adress0: R516.2 R517.1 ; sheet I2C_Expander_10/A0
GPIO_Exp13_Adress1: R518.2 R519.1 ; sheet I2C_Expander_10/A1
GPIO_Exp13_Adress2: R520.2 R521.1 ; sheet I2C_Expander_10/A2
GPIO_Exp13_Int0: sheet I2C_Expander_10/IntA, port Exp_Int.Int0
GPIO_Exp13_Int1: sheet I2C_Expander_10/IntB, port Exp_Int.Int1
GPIO_Exp14_Adress0: R524.2 R525.1 ; sheet I2C_Expander_11/A0
GPIO_Exp14_Adress1: R526.2 R527.1 ; sheet I2C_Expander_11/A1
GPIO_Exp14_Adress2: R528.2 R529.1 ; sheet I2C_Expander_11/A2
GPIO_Exp14_Int0: sheet I2C_Expander_11/IntA, port Exp_Int.Int2
GPIO_Exp14_Int1: sheet I2C_Expander_11/IntB, port Exp_Int.Int3
GPIO_Exp15_Adress0: R697.2 R698.1 ; sheet I2C_Expander_12/A0
GPIO_Exp15_Adress1: R699.2 R700.1 ; sheet I2C_Expander_12/A1
GPIO_Exp15_Adress2: R701.2 R702.1 ; sheet I2C_Expander_12/A2
GPIO_Exp15_Int0: sheet I2C_Expander_12/IntA, port Exp_Int.Int4
GPIO_Exp15_Int1: sheet I2C_Expander_12/IntB, port Exp_Int.Int5
GPIO_Exp_Reset1: port GPIO_Reset, sheet I2C_Expander_10/~{RESET}, sheet I2C_Expander_11/~{RESET}, sheet I2C_Expander_12/~{RESET}
GPIOa_10.GPIO1: sheet I2C_Expander_10/IOA1, port GPIO0.GPIO1
GPIOa_10.GPIO2: sheet I2C_Expander_10/IOA2, port GPIO0.GPIO2
GPIOa_10.GPIO3: sheet I2C_Expander_10/IOA3, port GPIO0.GPIO3
GPIOa_10.GPIO4: sheet I2C_Expander_10/IOA4, port GPIO0.GPIO4
GPIOa_10.GPIO5: sheet I2C_Expander_10/IOA5, port GPIO0.GPIO5
GPIOa_10.GPIO6: sheet I2C_Expander_10/IOA6, port GPIO0.GPIO6
GPIOa_10.GPIO7: sheet I2C_Expander_10/IOA7, port GPIO0.GPIO7
GPIOa_11.GPIO1: sheet I2C_Expander_11/IOA1, port GPIO2.GPIO1
GPIOa_11.GPIO4: sheet I2C_Expander_11/IOA4, port GPIO2.GPIO4
GPIOa_11.GPIO6: sheet I2C_Expander_11/IOA6, port GPIO2.GPIO6
GPIOa_11.GPIO7: sheet I2C_Expander_11/IOA7, port GPIO2.GPIO7
GPIOb_10.GPIO0: sheet I2C_Expander_10/IOB0, port GPIO1.GPIO0
GPIOb_10.GPIO1: sheet I2C_Expander_10/IOB1, port GPIO1.GPIO1
GPIOb_10.GPIO3: sheet I2C_Expander_10/IOB3, port GPIO1.GPIO3
GPIOb_10.GPIO4: sheet I2C_Expander_10/IOB4, port GPIO1.GPIO4
GPIOb_10.GPIO6: sheet I2C_Expander_10/IOB6, port GPIO1.GPIO6
GPIOb_11.GPIO1: sheet I2C_Expander_11/IOB1, port GPIO3.GPIO1
GPIOb_11.GPIO2: sheet I2C_Expander_11/IOB2, port GPIO3.GPIO2
GPIOb_11.GPIO4: sheet I2C_Expander_11/IOB4, port GPIO3.GPIO4
GPIOb_11.GPIO5: sheet I2C_Expander_11/IOB5, port GPIO3.GPIO5
GPIOb_11.GPIO6: sheet I2C_Expander_11/IOB6, port GPIO3.GPIO6
GPIOb_12.GPIO1: sheet I2C_Expander_12/IOB1, port GPIO5.GPIO1
GPIOb_12.GPIO2: sheet I2C_Expander_12/IOB2, port GPIO5.GPIO2
GPIOb_12.GPIO3: sheet I2C_Expander_12/IOB3, port GPIO5.GPIO3
GPIOb_12.GPIO4: sheet I2C_Expander_12/IOB4, port GPIO5.GPIO4
GPIOb_12.GPIO5: sheet I2C_Expander_12/IOB5, port GPIO5.GPIO5
GPIOb_12.GPIO7: sheet I2C_Expander_12/IOB7, port GPIO5.GPIO7

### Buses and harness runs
harness port I2C = sheet I2C_Expander_10/I2C = sheet I2C_Expander_11/I2C = sheet I2C_Expander_12/I2C

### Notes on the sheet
- (near R521) 0x40
- (near R529) 0x42
- (near R702) 0x44

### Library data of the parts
R516 R518 R520 R524 R526 R528 R697 R699 R701 = Resistor: as R492 on sheet Ext_GPIO_Bank0
R517 R519 R521 R525 R527 R529 R698 R700 R702 = Resistor: as R665 on sheet Power_48_20V@3A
